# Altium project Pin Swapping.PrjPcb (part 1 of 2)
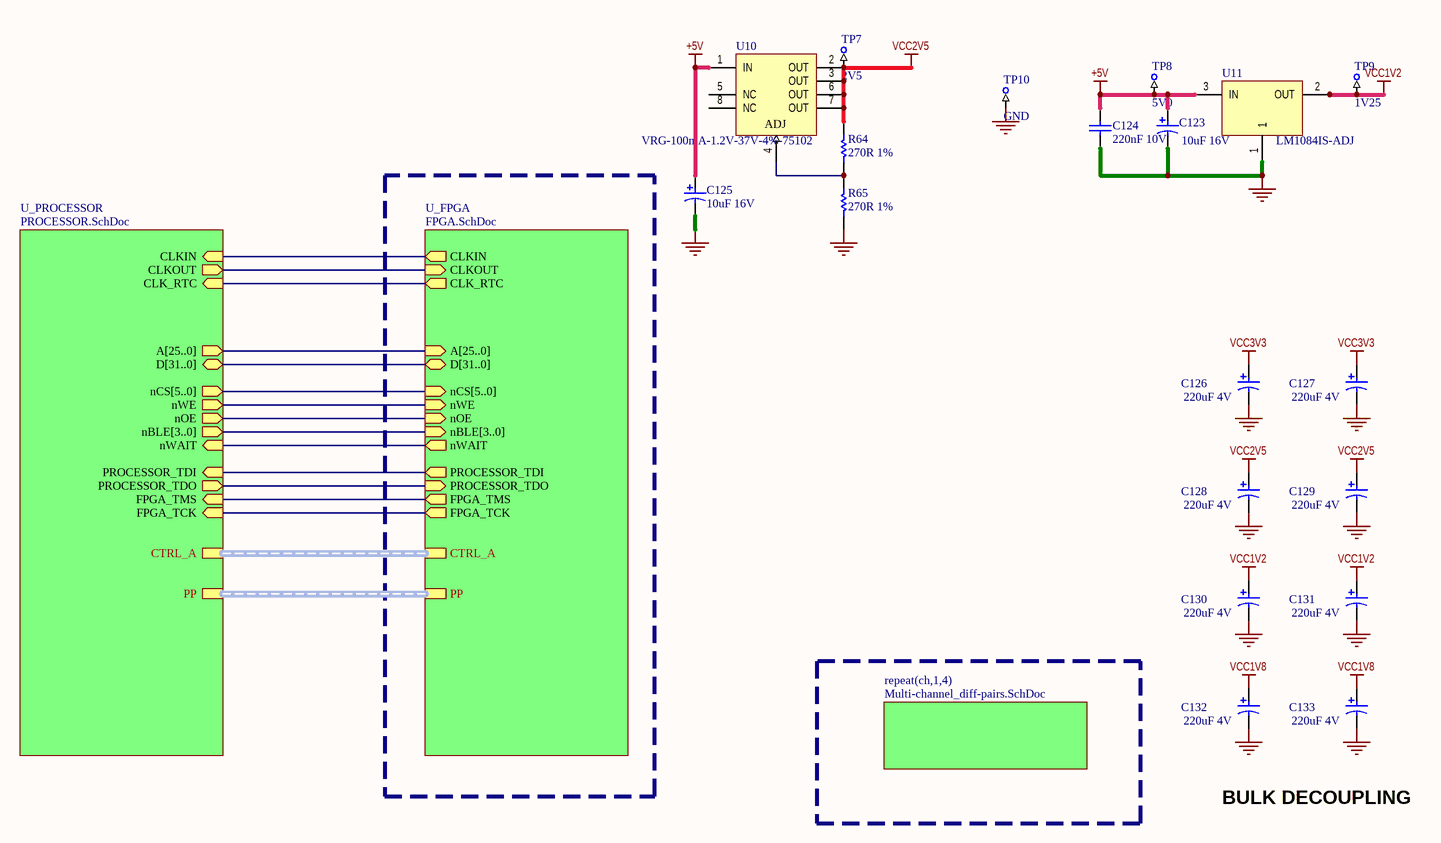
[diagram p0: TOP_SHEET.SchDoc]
6 sheets, 254 parts. Net scope: hierarchical (ports join the sheet entries above them; power ports are global).
Board file: NBP-28 Pin_Swap_Example.PcbDoc
Sheets:
  TOP_SHEET.SchDoc
    U_PROCESSOR = PROCESSOR.SchDoc
      U_PROCESSOR_MEMORIES = PROCESSOR_MEMORIES.SchDoc
    U_FPGA = FPGA.SchDoc
      U_FPGA_RAM = FPGA_MEMORIES.SchDoc
    ch1 = Multi-channel_diff-pairs.SchDoc
    ch2 = Multi-channel_diff-pairs.SchDoc
    ch3 = Multi-channel_diff-pairs.SchDoc
    ch4 = Multi-channel_diff-pairs.SchDoc

## Sheet TOP_SHEET.SchDoc: Pin Swapping
size 431 x 279 mm; DocumentNumber: 1; SheetNumber: 1; SheetTotal: 5

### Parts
C123  10uF 16V  [CAPC3528]
C124  220nF 10V  [CAPC1608]
C125  10uF 16V  [CAPC3528]
C126  220uF 4V  [CAPC7343]
C127  220uF 4V  [CAPC7343]
C128  220uF 4V  [CAPC7343]
C129  220uF 4V  [CAPC7343]
C130  220uF 4V  [CAPC7343]
C131  220uF 4V  [CAPC7343]
C132  220uF 4V  [CAPC7343]
C133  220uF 4V  [CAPC7343]
R64  270R 1%  [RESC2012]
R65  270R 1%  [RESC2012]
TP7  2V5  [TestPin]  (no BOM)
TP8  5V0  [TestPin]  (no BOM)
TP9  1V25  [TestPin]  (no BOM)
TP10  GND  [TestPin]  (no BOM)
U10  VRG-100mA-1.2V-37V-4%-75102  [SOP127P600-8]
U11  LM1084IS-ADJ  [TO254P1435-4]

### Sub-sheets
repeat(ch,1,4) = Multi-channel_diff-pairs.SchDoc: no entries
U_FPGA = FPGA.SchDoc: FPGA_TMS (out), FPGA_TCK (out), PROCESSOR_TDO (in), PROCESSOR_TDI (out), CLKIN (out), A[25..0] (in), D[31..0] (bidir), nBLE[3..0] (in), nWE (in), nOE (in), nCS[5..0] (in), nWAIT (out), CLKOUT (in), CLK_RTC (out), PP (harness PP_13_LINES), CTRL_A (harness P_C_HARNESS)
U_PROCESSOR = PROCESSOR.SchDoc: A[25..0] (out), D[31..0] (bidir), CLKOUT (out), PROCESSOR_TDO (out), PROCESSOR_TDI (in), nBLE[3..0] (out), nWE (out), nOE (out), nCS[5..0] (out), nWAIT (in), CLKIN (in), FPGA_TMS (in), FPGA_TCK (in), CLK_RTC (in), PP (harness PP_13_LINES), CTRL_A (harness P_C_HARNESS)

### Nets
+5V: C123.1 C124.1 C125.1 TP8.1 U10.1(IN) U11.3(IN)
GND: C123.2 C124.2 C125.2 C126.2 C127.2 C128.2 C129.2 C130.2 C131.2 C132.2 C133.2 R65.2 TP10.1 U11.1
VCC1V2: C130.1 C131.1 TP9.1 U11.2(OUT) U11.4(HeatSink)
VCC1V8: C132.1 C133.1
VCC2V5: C128.1 C129.1 R64.1 TP7.1 U10.2(OUT) U10.3(OUT) U10.6(OUT) U10.7(OUT)
VCC3V3: C126.1 C127.1
CLK_RTC: sheet U_PROCESSOR/CLK_RTC, sheet U_FPGA/CLK_RTC
CLKIN: sheet U_PROCESSOR/CLKIN, sheet U_FPGA/CLKIN
CLKOUT: sheet U_PROCESSOR/CLKOUT, sheet U_FPGA/CLKOUT
FPGA_TCK: sheet U_PROCESSOR/FPGA_TCK, sheet U_FPGA/FPGA_TCK
FPGA_TMS: sheet U_PROCESSOR/FPGA_TMS, sheet U_FPGA/FPGA_TMS
nOE: sheet U_PROCESSOR/nOE, sheet U_FPGA/nOE
nWAIT: sheet U_PROCESSOR/nWAIT, sheet U_FPGA/nWAIT
nWE: sheet U_PROCESSOR/nWE, sheet U_FPGA/nWE
PROCESSOR_TDI: sheet U_PROCESSOR/PROCESSOR_TDI, sheet U_FPGA/PROCESSOR_TDI
PROCESSOR_TDO: sheet U_PROCESSOR/PROCESSOR_TDO, sheet U_FPGA/PROCESSOR_TDO
NetR64_2: R64.2 R65.1 U10.4(ADJ)

Not connected (* = marked no-connect by the designer): U10 5(NC) 8(NC)

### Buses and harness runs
bus sheet U_FPGA/A[25..0] = sheet U_PROCESSOR/A[25..0]
bus sheet U_FPGA/D[31..0] = sheet U_PROCESSOR/D[31..0]
bus sheet U_FPGA/nBLE[3..0] = sheet U_PROCESSOR/nBLE[3..0]
bus sheet U_FPGA/nCS[5..0] = sheet U_PROCESSOR/nCS[5..0]
harness sheet U_FPGA/CTRL_A = sheet U_PROCESSOR/CTRL_A
harness sheet U_FPGA/PP = sheet U_PROCESSOR/PP

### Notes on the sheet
- BULK DECOUPLING

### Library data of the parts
C123 C125-C133 = CAP-P: Polar Capacitor
C124 = CAP-NP: Capacitor
R64 R65 = RES: Resistor
TP7-TP10 = TestPin
U10 = VRG-ADJ-8: Low Current 3-Terminal Adjustable Positive Voltage Regulator
U11 = VRG-ADJ-3: 5A Low Dropout Positive Regulators

## Sheet PROCESSOR.SchDoc: Pin Swapping
size 558 x 431 mm; DocumentNumber: 2; SheetNumber: 2; SheetTotal: 6
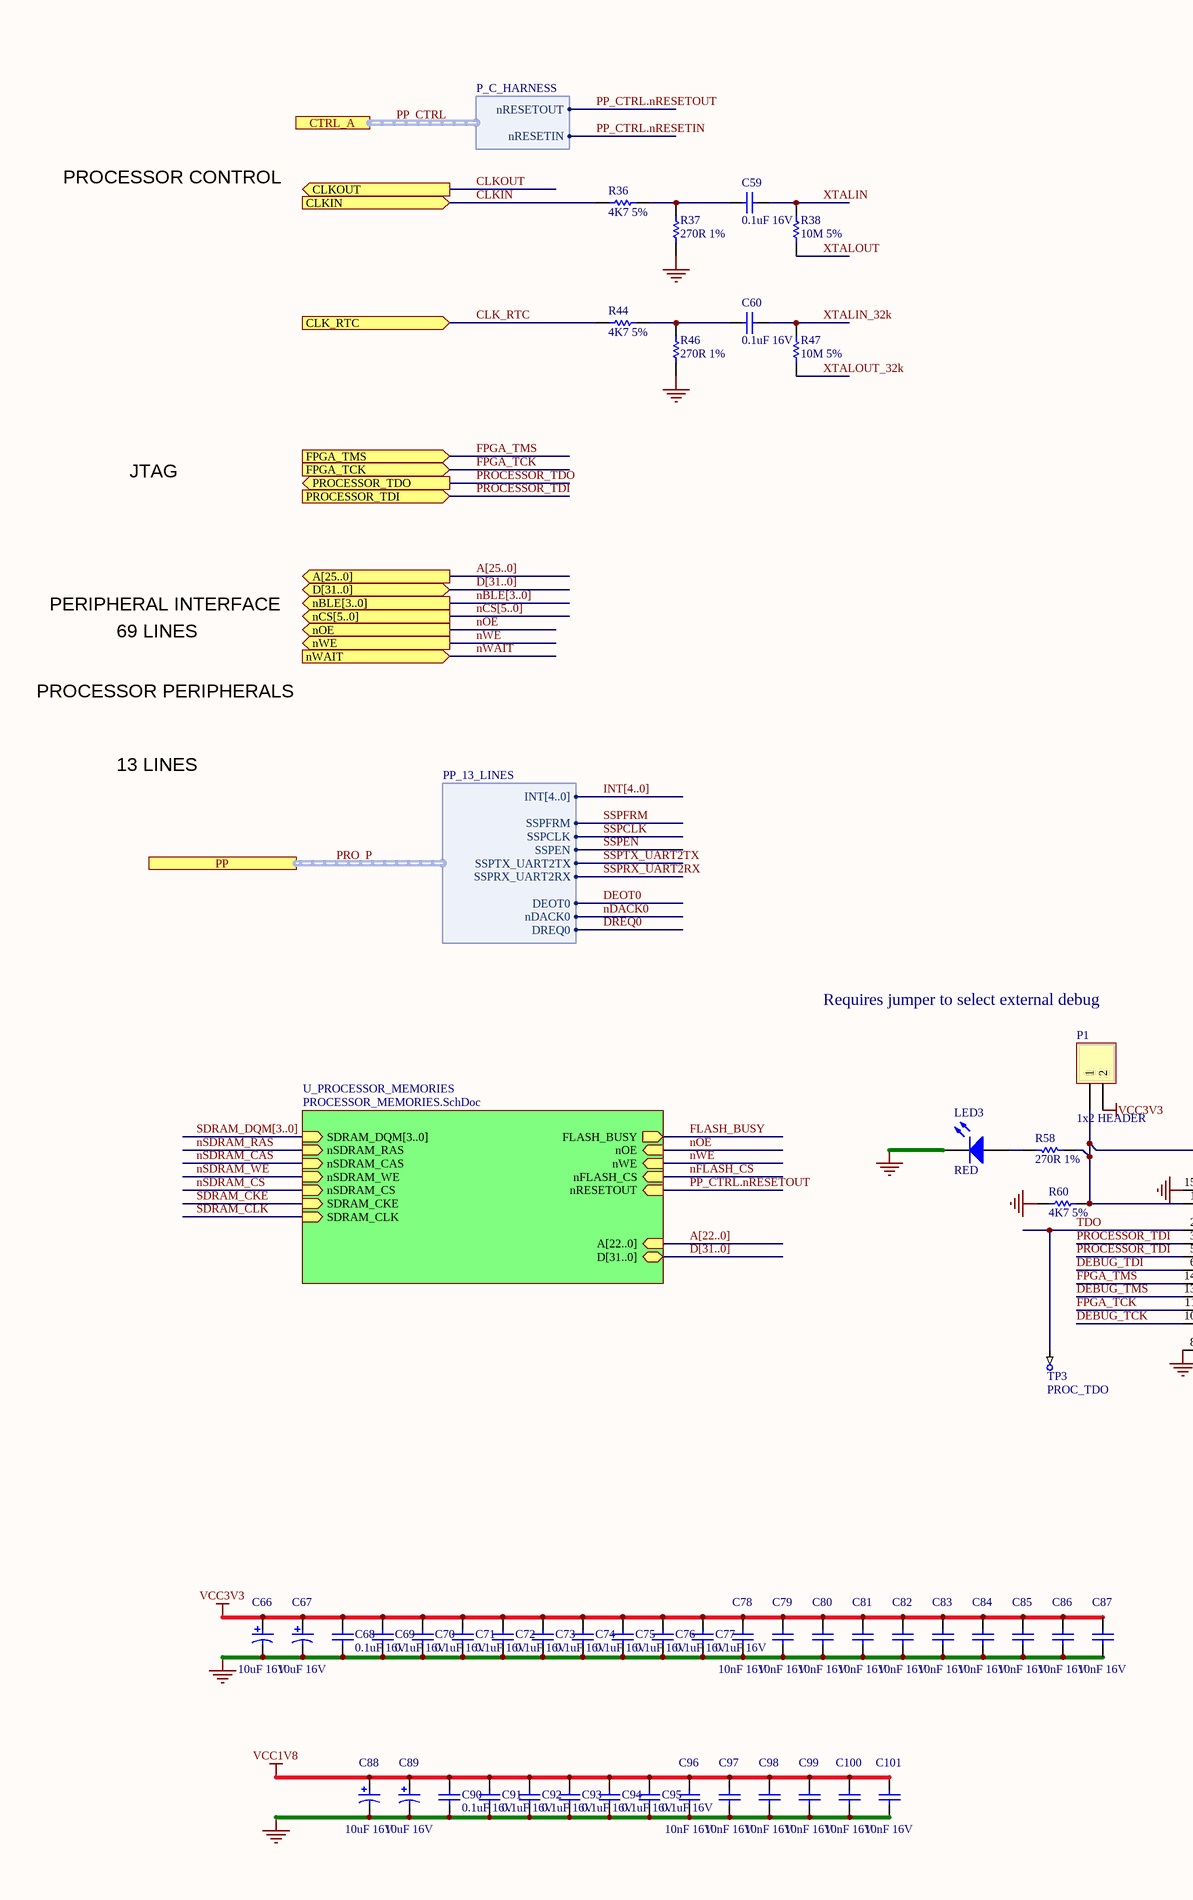
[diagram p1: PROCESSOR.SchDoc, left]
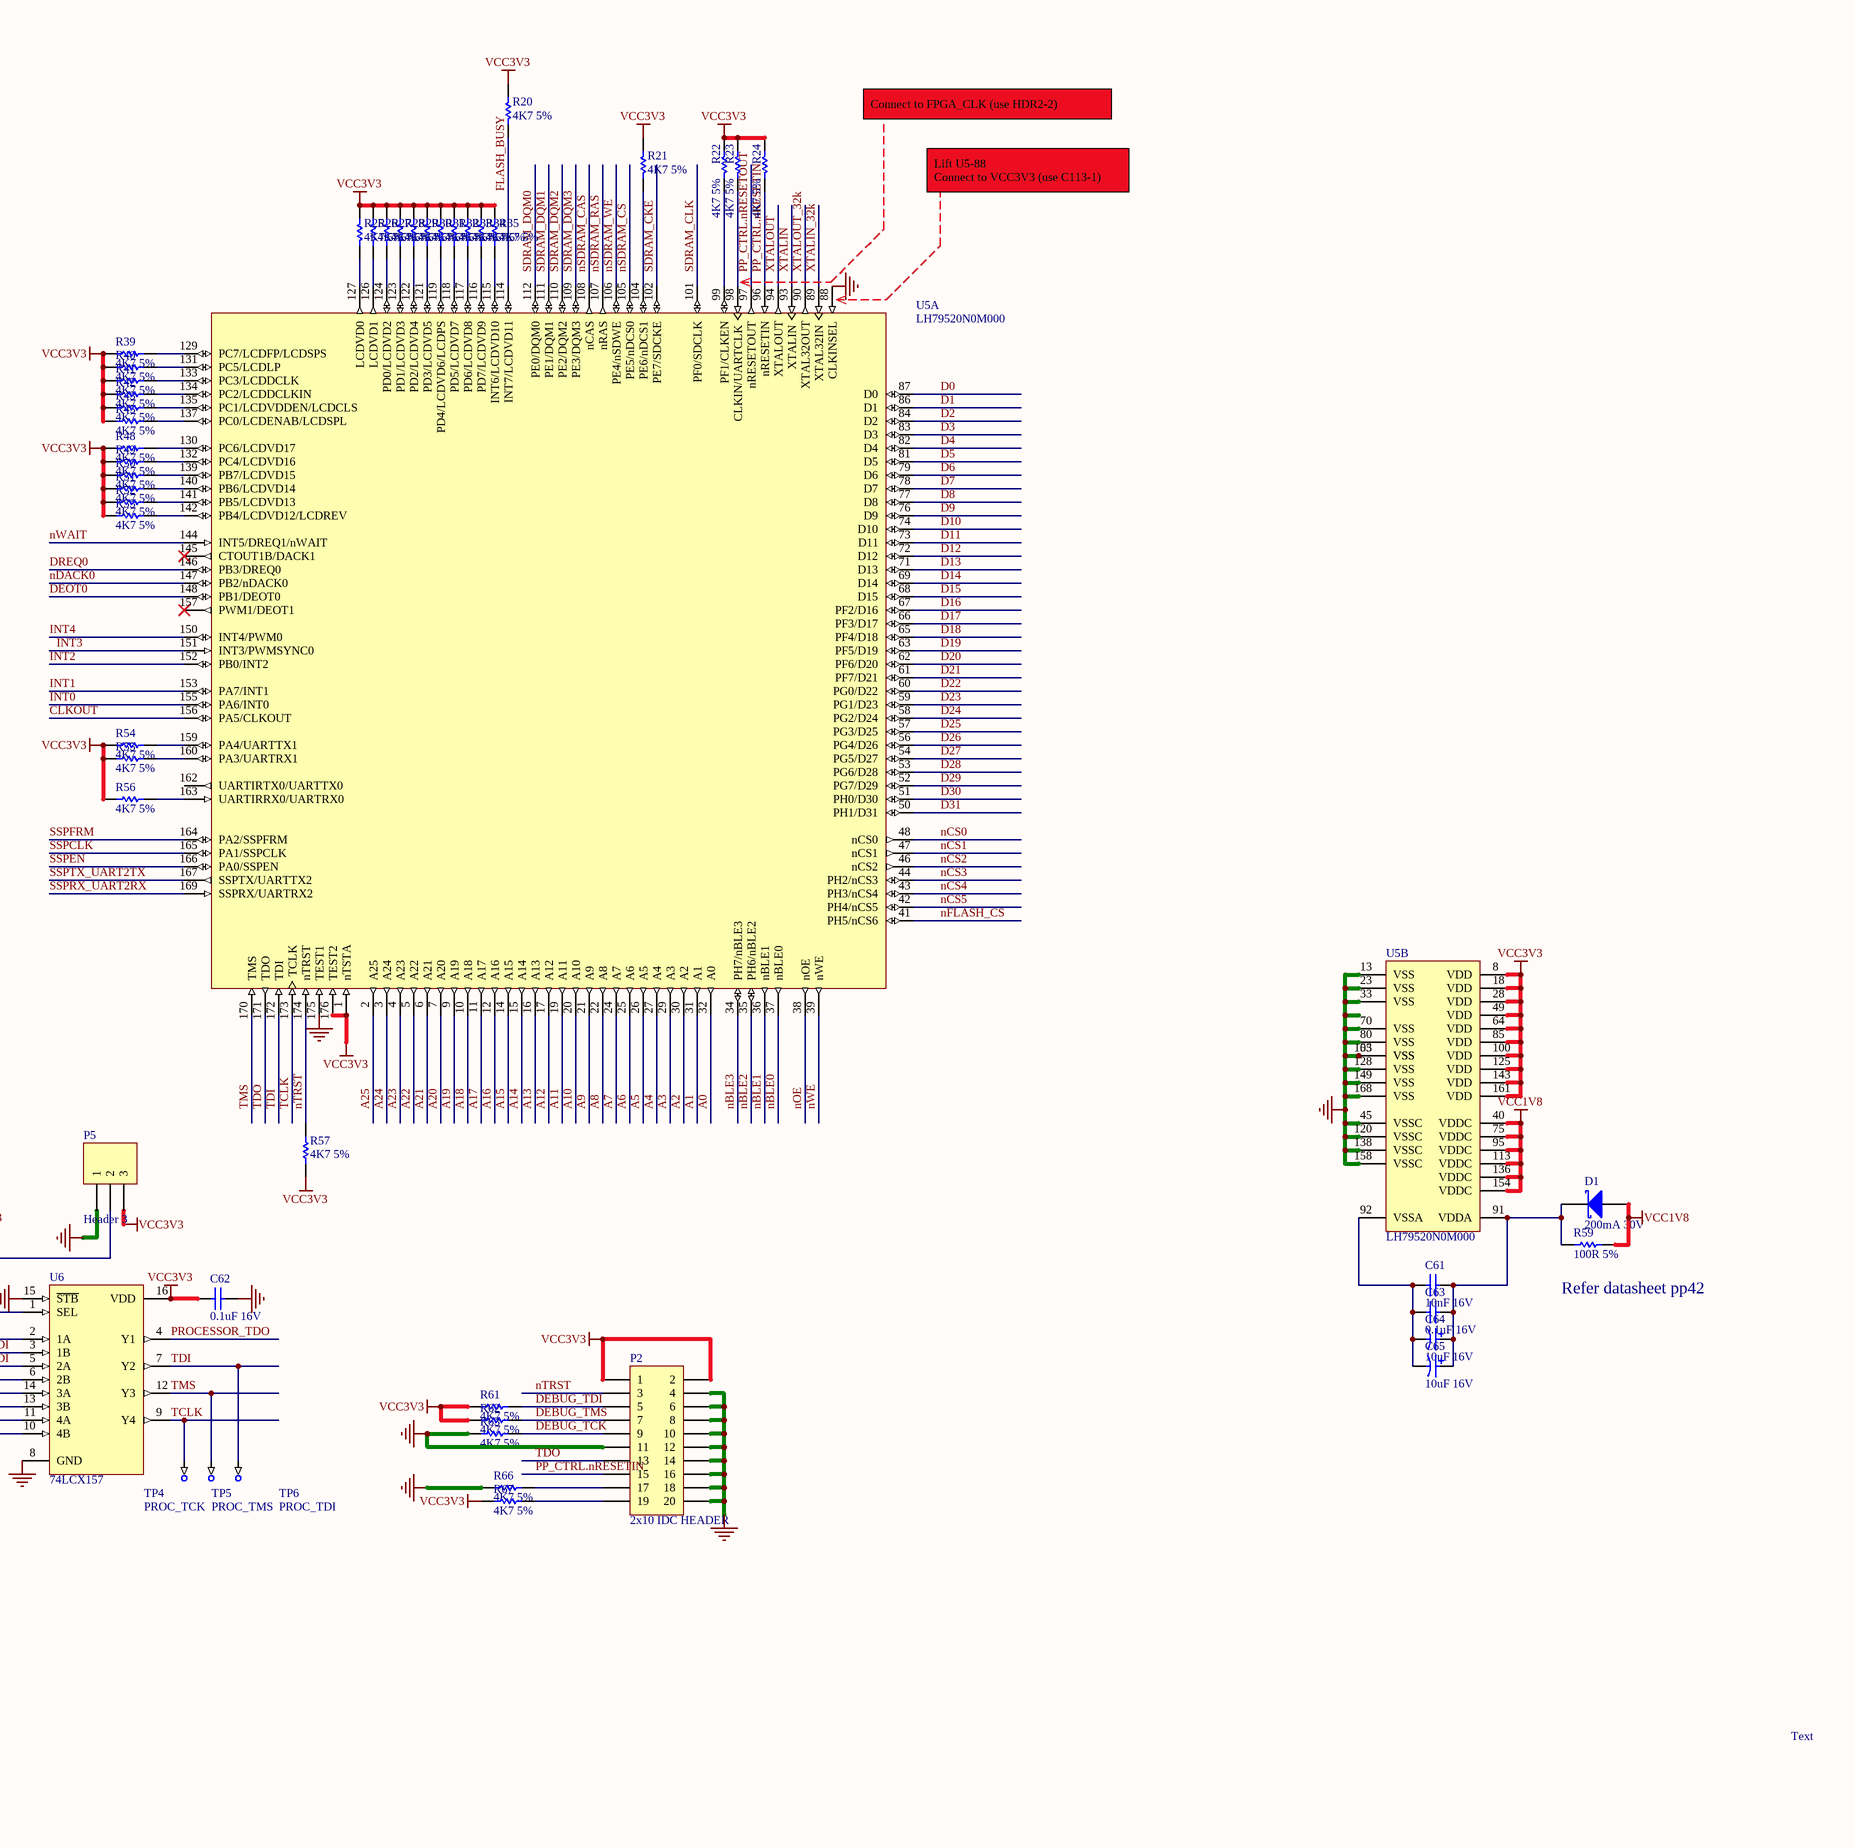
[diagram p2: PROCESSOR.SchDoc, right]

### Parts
C59  0.1uF 16V  [CAPC1005]
C60  0.1uF 16V  [CAPC1005]
C61  10nF 16V  [CAPC1005]
C62  0.1uF 16V  [CAPC1005]
C63  0.1uF 16V  [CAPC1005]
C64  10uF 16V  [CAPC3528]
C65  10uF 16V  [CAPC3528]
C66  10uF 16V  [CAPC3528]
C67  10uF 16V  [CAPC3528]
C68  0.1uF 16V  [CAPC1005]
C69  0.1uF 16V  [CAPC1005]
C70  0.1uF 16V  [CAPC1005]
C71  0.1uF 16V  [CAPC1005]
C72  0.1uF 16V  [CAPC1005]
C73  0.1uF 16V  [CAPC1005]
C74  0.1uF 16V  [CAPC1005]
C75  0.1uF 16V  [CAPC1005]
C76  0.1uF 16V  [CAPC1005]
C77  0.1uF 16V  [CAPC1005]
C78  10nF 16V  [CAPC1005]
C79  10nF 16V  [CAPC1005]
C80  10nF 16V  [CAPC1005]
C81  10nF 16V  [CAPC1005]
C82  10nF 16V  [CAPC1005]
C83  10nF 16V  [CAPC1005]
C84  10nF 16V  [CAPC1005]
C85  10nF 16V  [CAPC1005]
C86  10nF 16V  [CAPC1005]
C87  10nF 16V  [CAPC1005]
C88  10uF 16V  [CAPC3528]
C89  10uF 16V  [CAPC3528]
C90  0.1uF 16V  [CAPC1005]
C91  0.1uF 16V  [CAPC1005]
C92  0.1uF 16V  [CAPC1005]
C93  0.1uF 16V  [CAPC1005]
C94  0.1uF 16V  [CAPC1005]
C95  0.1uF 16V  [CAPC1005]
C96  10nF 16V  [CAPC1005]
C97  10nF 16V  [CAPC1005]
C98  10nF 16V  [CAPC1005]
C99  10nF 16V  [CAPC1005]
C100  10nF 16V  [CAPC1005]
C101  10nF 16V  [CAPC1005]
D1  200mA 30V  [SOT95P230-3]
LED3  RED  [LED2013]
P1  1x2 HEADER  [HDR1X2]
P2  2x10 IDC HEADER  [IDC2.54-V20D]
P5  Header 3  [HDR1X3]
R20  4K7 5%  [RESC1005]
R21  4K7 5%  [RESC1005]
R22  4K7 5%  [RESC1005]
R23  4K7 5%  [RESC1005]
R24  4K7 5%  [RESC1005]
R25  4K7 5%  [RESC1005]
R26  4K7 5%  [RESC1005]
R27  4K7 5%  [RESC1005]
R28  4K7 5%  [RESC1005]
R29  4K7 5%  [RESC1005]
R30  4K7 5%  [RESC1005]
R31  4K7 5%  [RESC1005]
R32  4K7 5%  [RESC1005]
R33  4K7 5%  [RESC1005]
R34  4K7 5%  [RESC1005]
R35  4K7 5%  [RESC1005]
R36  4K7 5%  [RESC1005]
R37  270R 1%  [RESC2012]
R38  10M 5%  [RESC2012]
R39  4K7 5%  [RESC1005]
R40  4K7 5%  [RESC1005]
R41  4K7 5%  [RESC1005]
R42  4K7 5%  [RESC1005]
R43  4K7 5%  [RESC1005]
R44  4K7 5%  [RESC1005]
R45  4K7 5%  [RESC1005]
R46  270R 1%  [RESC2012]
R47  10M 5%  [RESC2012]
R48  4K7 5%  [RESC1005]
R49  4K7 5%  [RESC1005]
R50  4K7 5%  [RESC1005]
R51  4K7 5%  [RESC1005]
R52  4K7 5%  [RESC1005]
R53  4K7 5%  [RESC1005]
R54  4K7 5%  [RESC1005]
R55  4K7 5%  [RESC1005]
R56  4K7 5%  [RESC1005]
R57  4K7 5%  [RESC1005]
R58  270R 1%  [RESC2012]
R59  100R 5%  [RESC2012]
R60  4K7 5%  [RESC1005]
R61  4K7 5%  [RESC1005]
R62  4K7 5%  [RESC1005]
R63  4K7 5%  [RESC1005]
R66  4K7 5%  [RESC1005]
R67  4K7 5%  [RESC1005]
TP3  PROC_TDO  [TestPin]  (no BOM)
TP4  PROC_TCK  [TestPin]  (no BOM)
TP5  PROC_TMS  [TestPin]  (no BOM)
TP6  PROC_TDI  [TestPin]  (no BOM)
U5  LH79520N0M000  [QFP40P2000X2000-176]  (parts A,B of 2)
U6  74LCX157  [TSOP65P638-16]

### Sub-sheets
U_PROCESSOR_MEMORIES = PROCESSOR_MEMORIES.SchDoc: SDRAM_DQM[3..0] (in), nSDRAM_RAS (in), nSDRAM_CAS (in), nSDRAM_WE (in), nSDRAM_CS (in), SDRAM_CKE (in), SDRAM_CLK (in), A[22..0] (in), D[31..0] (bidir), nOE (in), nWE (in), nFLASH_CS (in), nRESETOUT (in), FLASH_BUSY (out)

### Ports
A[25..0] (out), CLK_RTC (in), CLKIN (in), CLKOUT (out), CTRL_A (harness P_C_HARNESS), D[31..0] (bidir), FPGA_TCK (in), FPGA_TMS (in), nBLE[3..0] (out), nCS[5..0] (out), nOE (out), nWAIT (in), nWE (out), PP (harness PP_13_LINES), PROCESSOR_TDI (in), PROCESSOR_TDO (out)

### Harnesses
PP_13_LINES: INT[4..0], SSPFRM, SSPCLK, SSPEN, SSPTX_UART2TX, SSPRX_UART2RX, DEOT0, nDACK0, DREQ0
P_C_HARNESS: nRESETOUT, nRESETIN

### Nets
GND: C62.2 C66.2 C67.2 C68.2 C69.2 C70.2 C71.2 C72.2 C73.2 C74.2 C75.2 C76.2 C77.2 C78.2 C79.2 C80.2 C81.2 C82.2 C83.2 C84.2 C85.2 C86.2 C87.2 C88.2 C89.2 C90.2 C91.2 C92.2 C93.2 C94.2 C95.2 C96.2 C97.2 C98.2 C99.2 C100.2 C101.2 LED3.2(K) P2.4 P2.6 P2.8 P2.10 P2.11 P2.12 P2.14 P2.16 P2.18 P2.20 P5.1 R37.1 R46.1 R60.2 R63.1 R66.1 U5.13(VSS) U5.23(VSS) U5.33(VSS) U5.45(VSSC) U5.55(VSS) U5.70(VSS) U5.80(VSS) U5.88(CLKINSEL) U5.103(VSS) U5.120(VSSC) U5.128(VSS) U5.138(VSSC) U5.149(VSS) U5.158(VSSC) U5.168(VSS) U5.175(TEST1) U6.8(GND) U6.15(~{STB})
VCC1V8: C88.1 C89.1 C90.1 C91.1 C92.1 C93.1 C94.1 C95.1 C96.1 C97.1 C98.1 C99.1 C100.1 C101.1 D1.1(A) R59.1 U5.40(VDDC) U5.75(VDDC) U5.95(VDDC) U5.113(VDDC) U5.136(VDDC) U5.154(VDDC)
VCC3V3: C62.1 C66.1 C67.1 C68.1 C69.1 C70.1 C71.1 C72.1 C73.1 C74.1 C75.1 C76.1 C77.1 C78.1 C79.1 C80.1 C81.1 C82.1 C83.1 C84.1 C85.1 C86.1 C87.1 P1.2 P2.1 P2.2 P5.3 R20.2 R21.2 R22.2 R23.2 R24.2 R25.2 R26.2 R27.2 R28.2 R29.2 R30.2 R31.2 R32.2 R33.2 R34.2 R35.2 R39.2 R40.2 R41.2 R42.2 R43.2 R45.2 R48.2 R49.2 R50.2 R51.2 R52.2 R53.2 R54.2 R55.2 R56.2 R57.2 R61.1 R62.1 R67.1 U5.1(nTSTA) U5.8(VDD) U5.18(VDD) U5.28(VDD) U5.49(VDD) U5.64(VDD) U5.85(VDD) U5.100(VDD) U5.125(VDD) U5.143(VDD) U5.161(VDD) U5.176(TEST2) U6.16(VDD)
A0: U5.32(A0)
A1: U5.31(A1)
A2: U5.30(A2)
A3: U5.29(A3)
A4: U5.27(A4)
A5: U5.26(A5)
A6: U5.25(A6)
A7: U5.24(A7)
A8: U5.22(A8)
A9: U5.21(A9)
A10: U5.20(A10)
A11: U5.19(A11)
A12: U5.17(A12)
A13: U5.16(A13)
A14: U5.15(A14)
A15: U5.14(A15)
A16: U5.12(A16)
A17: U5.11(A17)
A18: U5.10(A18)
A19: U5.9(A19)
A20: U5.7(A20)
A21: U5.6(A21)
A22: U5.5(A22)
A23: U5.4(A23)
A24: U5.3(A24)
A25: U5.2(A25)
CLK_RTC: R44.2 ; port CLK_RTC
CLKIN: R36.2 ; port CLKIN
CLKOUT: U5.156(PA5/CLKOUT) ; port CLKOUT
D0: U5.87(D0)
D1: U5.86(D1)
D2: U5.84(D2)
D3: U5.83(D3)
D4: U5.82(D4)
D5: U5.81(D5)
D6: U5.79(D6)
D7: U5.78(D7)
D8: U5.77(D8)
D9: U5.76(D9)
D10: U5.74(D10)
D11: U5.73(D11)
D12: U5.72(D12)
D13: U5.71(D13)
D14: U5.69(D14)
D15: U5.68(D15)
D16: U5.67(PF2/D16)
D17: U5.66(PF3/D17)
D18: U5.65(PF4/D18)
D19: U5.63(PF5/D19)
D20: U5.62(PF6/D20)
D21: U5.61(PF7/D21)
D22: U5.60(PG0/D22)
D23: U5.59(PG1/D23)
D24: U5.58(PG2/D24)
D25: U5.57(PG3/D25)
D26: U5.56(PG4/D26)
D27: U5.54(PG5/D27)
D28: U5.53(PG6/D28)
D29: U5.52(PG7/D29)
D30: U5.51(PH0/D30)
D31: U5.50(PH1/D31)
DEBUG_TCK: P2.9 R63.2 U6.10(4B)
DEBUG_TDI: P2.5 R61.2 U6.6(2B)
DEBUG_TMS: P2.7 R62.2 U6.13(3B)
DEOT0: U5.148(PB1/DEOT0) ; port PP.DEOT0
DREQ0: U5.146(PB3/DREQ0) ; port PP.DREQ0
FLASH_BUSY: R20.1 U5.114(INT7/LCDVD11) ; sheet U_PROCESSOR_MEMORIES/FLASH_BUSY
FPGA_TCK: U6.11(4A) ; port FPGA_TCK
FPGA_TMS: U6.14(3A) ; port FPGA_TMS
INT0: U5.155(PA6/INT0)
INT1: U5.153(PA7/INT1)
INT2: U5.152(PB0/INT2)
INT3: U5.151(INT3/PWMSYNC0)
INT4: U5.150(INT4/PWM0)
nBLE0: U5.37(nBLE0)
nBLE1: U5.36(nBLE1)
nBLE2: U5.35(PH6/nBLE2)
nBLE3: U5.34(PH7/nBLE3)
nCS0: U5.48(nCS0)
nCS1: U5.47(nCS1)
nCS2: U5.46(nCS2)
nCS3: U5.44(PH2/nCS3)
nCS4: U5.43(PH3/nCS4)
nCS5: U5.42(PH4/nCS5)
nDACK0: U5.147(PB2/nDACK0) ; port PP.nDACK0
nFLASH_CS: U5.41(PH5/nCS6) ; sheet U_PROCESSOR_MEMORIES/nFLASH_CS
nOE: U5.38(nOE) ; port nOE, sheet U_PROCESSOR_MEMORIES/nOE
nSDRAM_CAS: U5.108(nCAS) ; sheet U_PROCESSOR_MEMORIES/nSDRAM_CAS
nSDRAM_CS: U5.105(PE5/nDCS0) ; sheet U_PROCESSOR_MEMORIES/nSDRAM_CS
nSDRAM_RAS: U5.107(nRAS) ; sheet U_PROCESSOR_MEMORIES/nSDRAM_RAS
nSDRAM_WE: U5.106(PE4/nSDWE) ; sheet U_PROCESSOR_MEMORIES/nSDRAM_WE
nTRST: P2.3 R57.1 U5.174(nTRST)
nWAIT: U5.144(INT5/DREQ1/nWAIT) ; port nWAIT
nWE: U5.39(nWE) ; port nWE, sheet U_PROCESSOR_MEMORIES/nWE
PP_CTRL.nRESETIN: P2.15 R24.1 U5.96(nRESETIN) ; port CTRL_A.nRESETIN
PP_CTRL.nRESETOUT: U5.97(nRESETOUT) ; sheet U_PROCESSOR_MEMORIES/nRESETOUT, port CTRL_A.nRESETOUT  [project net nRESETOUT]
PROCESSOR_TDI: U6.3(1B) U6.5(2A) ; port PROCESSOR_TDI
PROCESSOR_TDO: U6.4(Y1) ; port PROCESSOR_TDO
SDRAM_CKE: U5.102(PE7/SDCKE) ; sheet U_PROCESSOR_MEMORIES/SDRAM_CKE
SDRAM_CLK: U5.101(PF0/SDCLK) ; sheet U_PROCESSOR_MEMORIES/SDRAM_CLK
SDRAM_DQM0: U5.112(PE0/DQM0)
SDRAM_DQM1: U5.111(PE1/DQM1)
SDRAM_DQM2: U5.110(PE2/DQM2)
SDRAM_DQM3: U5.109(PE3/DQM3)
SSPCLK: U5.165(PA1/SSPCLK) ; port PP.SSPCLK  [project net PRO_P.SSPCLK]
SSPEN: U5.166(PA0/SSPEN) ; port PP.SSPEN  [project net PRO_P.SSPEN]
SSPFRM: U5.164(PA2/SSPFRM) ; port PP.SSPFRM  [project net PRO_P.SSPFRM]
SSPRX_UART2RX: U5.169(SSPRX/UARTRX2) ; port PP.SSPRX_UART2RX  [project net PRO_P.SSPRX_UART2RX]
SSPTX_UART2TX: U5.167(SSPTX/UARTTX2) ; port PP.SSPTX_UART2TX  [project net PRO_P.SSPTX_UART2TX]
TCLK: TP4.1 U5.173(TCLK) U6.9(Y4)
TDI: TP6.1 U5.172(TDI) U6.7(Y2)
TDO: P2.13 TP3.1 U5.171(TDO) U6.2(1A)
TMS: TP5.1 U5.170(TMS) U6.12(Y3)
XTALIN: C59.2 R38.1 U5.93(XTALIN)
XTALIN_32k: C60.2 R47.1 U5.89(XTAL32IN)
XTALOUT: R38.2 U5.94(XTALOUT)
XTALOUT_32k: R47.2 U5.90(XTAL32OUT)
NetC59_1: C59.1 R36.1 R37.2
NetC60_1: C60.1 R44.1 R46.2
NetC61_1: C61.1 C63.1 C64.1 C65.1 D1.3(k) R59.2 U5.91(VDDA)
NetC61_2: C61.2 C63.2 C64.2 C65.2 U5.92(VSSA)
NetLED3_1: LED3.1(A) R58.2
NetP1_1: P1.1 P5.2 R58.1 R60.1 U6.1(SEL)
NetP2_17: P2.17 R66.2
NetP2_19: P2.19 R67.2
NetR21_1: R21.1 U5.104(PE6/nDCS1)
NetR22_1: R22.1 U5.99(PF1/CLKEN)
NetR23_1: R23.1 U5.98(CLKIN/UARTCLK)
NetR25_1: R25.1 U5.127(LCDVD0)
NetR26_1: R26.1 U5.126(LCDVD1)
NetR27_1: R27.1 U5.124(PD0/LCDVD2)
NetR28_1: R28.1 U5.123(PD1/LCDVD3)
NetR29_1: R29.1 U5.122(PD2/LCDVD4)
NetR30_1: R30.1 U5.121(PD3/LCDVD5)
NetR31_1: R31.1 U5.119(PD4/LCDVD6/LCDPS)
NetR32_1: R32.1 U5.118(PD5/LCDVD7)
NetR33_1: R33.1 U5.117(PD6/LCDVD8)
NetR34_1: R34.1 U5.116(PD7/LCDVD9)
NetR35_1: R35.1 U5.115(INT6/LCDVD10)
NetR39_1: R39.1 U5.129(PC7/LCDFP/LCDSPS)
NetR40_1: R40.1 U5.131(PC5/LCDLP)
NetR41_1: R41.1 U5.133(PC3/LCDDCLK)
NetR42_1: R42.1 U5.134(PC2/LCDDCLKIN)
NetR43_1: R43.1 U5.135(PC1/LCDVDDEN/LCDCLS)
NetR45_1: R45.1 U5.137(PC0/LCDENAB/LCDSPL)
NetR48_1: R48.1 U5.130(PC6/LCDVD17)
NetR49_1: R49.1 U5.132(PC4/LCDVD16)
NetR50_1: R50.1 U5.139(PB7/LCDVD15)
NetR51_1: R51.1 U5.140(PB6/LCDVD14)
NetR52_1: R52.1 U5.141(PB5/LCDVD13)
NetR53_1: R53.1 U5.142(PB4/LCDVD12/LCDREV)
NetR54_1: R54.1 U5.159(PA4/UARTTX1)
NetR55_1: R55.1 U5.160(PA3/UARTRX1)
NetR56_1: R56.1 U5.163(UARTIRRX0/UARTRX0)

Not connected (* = marked no-connect by the designer): D1 2; U5 145(CTOUT1B/DACK1)* 157(PWM1/DEOT1)* 162(UARTIRTX0/UARTTX0)

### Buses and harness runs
bus A[22..0] = sheet U_PROCESSOR_MEMORIES/A[22..0]
bus A[25..0] = port A[25..0]
bus D[31..0] = port D[31..0]
bus D[31..0] = sheet U_PROCESSOR_MEMORIES/D[31..0]
bus INT[4..0]
bus nBLE[3..0] = port nBLE[3..0]
bus nCS[5..0] = port nCS[5..0]
bus SDRAM_DQM[3..0] = sheet U_PROCESSOR_MEMORIES/SDRAM_DQM[3..0]
harness PP_CTRL = port CTRL_A
harness PRO_P = port PP

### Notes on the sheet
- Connect to FPGA_CLK (use HDR2-2)
- Lift U5-88
  Connect to VCC3V3 (use C113-1)
- PROCESSOR CONTROL
- JTAG
- PERIPHERAL INTERFACE
- 69 LINES
- PROCESSOR PERIPHERALS
- 13 LINES
- Requires jumper to select external debug
- (near R59) Refer datasheet pp42
- Text

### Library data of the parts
C59-C63 C68-C87 C90-C101 = CAP-NP: Capacitor
C64-C67 C88 C89 = CAP-P: Polar Capacitor
D1 = DIO-SCHOTTKY-1S-SOT23: Schottky Barrier Double Diode
LED3 = DIO-LED-1S: Typical GREEN SMD LED Agilent make
P1 = CON-HDR-1x2-STR: Header, 2-Pin
P2 = CON-IDC-2x10-M-STR: 10x2 IDC Male PCB Box Header
P5 = Header 3: Header, 3-Pin
R20-R63 R66 R67 = RES: Resistor
TP3-TP6 = TestPin
U5 = LH79520N0M000: 32-Bit ARM720T-Based BlueStreak MCU with 8KB Cache, MMU, Color LCD controller, 32KB SRAM, 176-Pin LQFP
U6 = 74LCX157-TSOP16: Quad 2-Input Multiplexer

## Sheet PROCESSOR_MEMORIES.SchDoc: Pin Swapping
size 431 x 279 mm; DocumentNumber: 3; SheetNumber: 3; SheetTotal: 5
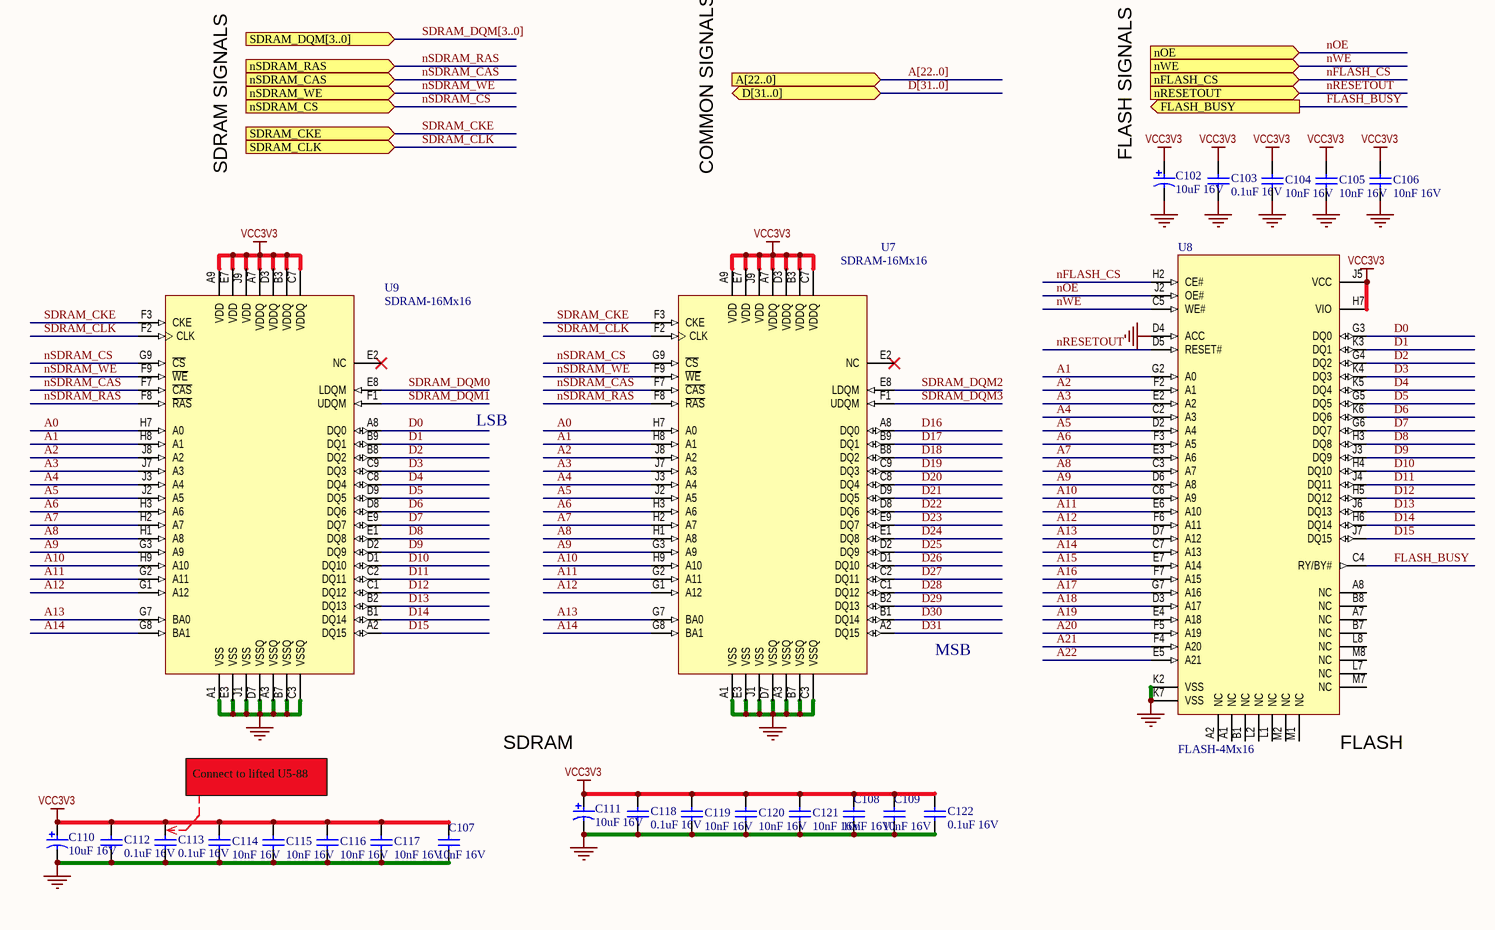
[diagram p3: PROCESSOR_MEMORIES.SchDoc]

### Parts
C102  10uF 16V  [CAPC3528]
C103  0.1uF 16V  [CAPC1005]
C104  10nF 16V  [CAPC1005]
C105  10nF 16V  [CAPC1005]
C106  10nF 16V  [CAPC1005]
C107  10nF 16V  [CAPC1005]
C108  10nF 16V  [CAPC1005]
C109  10nF 16V  [CAPC1005]
C110  10uF 16V  [CAPC3528]
C111  10uF 16V  [CAPC3528]
C112  0.1uF 16V  [CAPC1005]
C113  0.1uF 16V  [CAPC1005]
C114  10nF 16V  [CAPC1005]
C115  10nF 16V  [CAPC1005]
C116  10nF 16V  [CAPC1005]
C117  10nF 16V  [CAPC1005]
C118  0.1uF 16V  [CAPC1005]
C119  10nF 16V  [CAPC1005]
C120  10nF 16V  [CAPC1005]
C121  10nF 16V  [CAPC1005]
C122  0.1uF 16V  [CAPC1005]
U7  SDRAM-16Mx16  [BGA80P9X6-54]
U8  FLASH-4Mx16  [BGA80P12X8-63]
U9  SDRAM-16Mx16  [BGA80P9X6-54]

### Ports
A[22..0] (in), D[31..0] (bidir), FLASH_BUSY (out), nFLASH_CS (in), nOE (in), nRESETOUT (in), nSDRAM_CAS (in), nSDRAM_CS (in), nSDRAM_RAS (in), nSDRAM_WE (in), nWE (in), SDRAM_CKE (in), SDRAM_CLK (in), SDRAM_DQM[3..0] (in)

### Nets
GND: C102.2 C103.2 C104.2 C105.2 C106.2 C107.2 C108.2 C109.2 C110.2 C111.2 C112.2 C113.2 C114.2 C115.2 C116.2 C117.2 C118.2 C119.2 C120.2 C121.2 C122.2 U7.A1(VSS) U7.A3(VSSQ) U7.B7(VSSQ) U7.C3(VSSQ) U7.D7(VSSQ) U7.E3(VSS) U7.J1(VSS) U8.D4(ACC) U8.K2(VSS) U8.K7(VSS) U9.A1(VSS) U9.A3(VSSQ) U9.B7(VSSQ) U9.C3(VSSQ) U9.D7(VSSQ) U9.E3(VSS) U9.J1(VSS)
VCC3V3: C102.1 C103.1 C104.1 C105.1 C106.1 C107.1 C108.1 C109.1 C110.1 C111.1 C112.1 C113.1 C114.1 C115.1 C116.1 C117.1 C118.1 C119.1 C120.1 C121.1 C122.1 U7.A7(VDDQ) U7.A9(VDD) U7.B3(VDDQ) U7.C7(VDDQ) U7.D3(VDDQ) U7.E7(VDD) U7.J9(VDD) U8.H7(VIO) U8.J5(VCC) U9.A7(VDDQ) U9.A9(VDD) U9.B3(VDDQ) U9.C7(VDDQ) U9.D3(VDDQ) U9.E7(VDD) U9.J9(VDD)
A0: U7.H7(A0) U9.H7(A0)
A1: U7.H8(A1) U8.G2(A0) U9.H8(A1)
A2: U7.J8(A2) U8.F2(A1) U9.J8(A2)
A3: U7.J7(A3) U8.E2(A2) U9.J7(A3)
A4: U7.J3(A4) U8.C2(A3) U9.J3(A4)
A5: U7.J2(A5) U8.D2(A4) U9.J2(A5)
A6: U7.H3(A6) U8.F3(A5) U9.H3(A6)
A7: U7.H2(A7) U8.E3(A6) U9.H2(A7)
A8: U7.H1(A8) U8.C3(A7) U9.H1(A8)
A9: U7.G3(A9) U8.D6(A8) U9.G3(A9)
A10: U7.H9(A10) U8.C6(A9) U9.H9(A10)
A11: U7.G2(A11) U8.E6(A10) U9.G2(A11)
A12: U7.G1(A12) U8.F6(A11) U9.G1(A12)
A13: U7.G7(BA0) U8.D7(A12) U9.G7(BA0)
A14: U7.G8(BA1) U8.C7(A13) U9.G8(BA1)
A15: U8.E7(A14)
A16: U8.F7(A15)
A17: U8.G7(A16)
A18: U8.D3(A17)
A19: U8.E4(A18)
A20: U8.F5(A19)
A21: U8.F4(A20)
A22: U8.E5(A21)
D0: U8.G3(DQ0) U9.A8(DQ0)
D1: U8.K3(DQ1) U9.B9(DQ1)
D2: U8.G4(DQ2) U9.B8(DQ2)
D3: U8.K4(DQ3) U9.C9(DQ3)
D4: U8.K5(DQ4) U9.C8(DQ4)
D5: U8.G5(DQ5) U9.D9(DQ5)
D6: U8.K6(DQ6) U9.D8(DQ6)
D7: U8.G6(DQ7) U9.E9(DQ7)
D8: U8.H3(DQ8) U9.E1(DQ8)
D9: U8.J3(DQ9) U9.D2(DQ9)
D10: U8.H4(DQ10) U9.D1(DQ10)
D11: U8.J4(DQ11) U9.C2(DQ11)
D12: U8.H5(DQ12) U9.C1(DQ12)
D13: U8.J6(DQ13) U9.B2(DQ13)
D14: U8.H6(DQ14) U9.B1(DQ14)
D15: U8.J7(DQ15) U9.A2(DQ15)
D16: U7.A8(DQ0)
D17: U7.B9(DQ1)
D18: U7.B8(DQ2)
D19: U7.C9(DQ3)
D20: U7.C8(DQ4)
D21: U7.D9(DQ5)
D22: U7.D8(DQ6)
D23: U7.E9(DQ7)
D24: U7.E1(DQ8)
D25: U7.D2(DQ9)
D26: U7.D1(DQ10)
D27: U7.C2(DQ11)
D28: U7.C1(DQ12)
D29: U7.B2(DQ13)
D30: U7.B1(DQ14)
D31: U7.A2(DQ15)
FLASH_BUSY: U8.C4(RY/BY#) ; port FLASH_BUSY
nFLASH_CS: U8.H2(CE#) ; port nFLASH_CS
nOE: U8.J2(OE#) ; port nOE
nRESETOUT: U8.D5(RESET#) ; port nRESETOUT
nSDRAM_CAS: U7.F7(~{CAS}) U9.F7(~{CAS}) ; port nSDRAM_CAS
nSDRAM_CS: U7.G9(~{CS}) U9.G9(~{CS}) ; port nSDRAM_CS
nSDRAM_RAS: U7.F8(~{RAS}) U9.F8(~{RAS}) ; port nSDRAM_RAS
nSDRAM_WE: U7.F9(~{WE}) U9.F9(~{WE}) ; port nSDRAM_WE
nWE: U8.C5(WE#) ; port nWE
SDRAM_CKE: U7.F3(CKE) U9.F3(CKE) ; port SDRAM_CKE
SDRAM_CLK: U7.F2(CLK) U9.F2(CLK) ; port SDRAM_CLK
SDRAM_DQM0: U9.E8(LDQM)
SDRAM_DQM1: U9.F1(UDQM)
SDRAM_DQM2: U7.E8(LDQM)
SDRAM_DQM3: U7.F1(UDQM)

Not connected (* = marked no-connect by the designer): U7 E2(NC)*; U8 A1(NC) A2(NC) A7(NC) A8(NC) B1(NC) B7(NC) B8(NC) L1(NC) L2(NC) L7(NC) L8(NC) M1(NC) M2(NC) M7(NC) M8(NC); U9 E2(NC)*

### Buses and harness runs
bus A[22..0] = port A[22..0]
bus D[31..0] = port D[31..0]
bus SDRAM_DQM[3..0] = port SDRAM_DQM[3..0]

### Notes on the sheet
- SDRAM SIGNALS
- COMMON SIGNALS
- (near C102) FLASH SIGNALS
- LSB
- MSB
- Connect to lifted U5-88
- SDRAM
- (near U8) FLASH

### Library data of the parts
C102 C110 C111 = CAP-P: Polar Capacitor
C103-C109 C112-C122 = CAP-NP: Capacitor
U7 U9 = MT48LC16M16A2FG: 256Mb Synchronous High-Speed CMOS DRAM, 16Mb x 16Bit x 4 Banks, 54-Ball FPGA, Commercial
U8 = AM29LV640DU90RWHI: 64 Mb (4 M x 16) CMOS 3.0 Volt, Uniform Sector Flash Memory with VersatileI/O Control, 63-ball FBGA, Industrial Grade

## Sheet FPGA.SchDoc: Pin Swapping
size 863 x 558 mm; DocumentNumber: 4; SheetNumber: 4; SheetTotal: 6
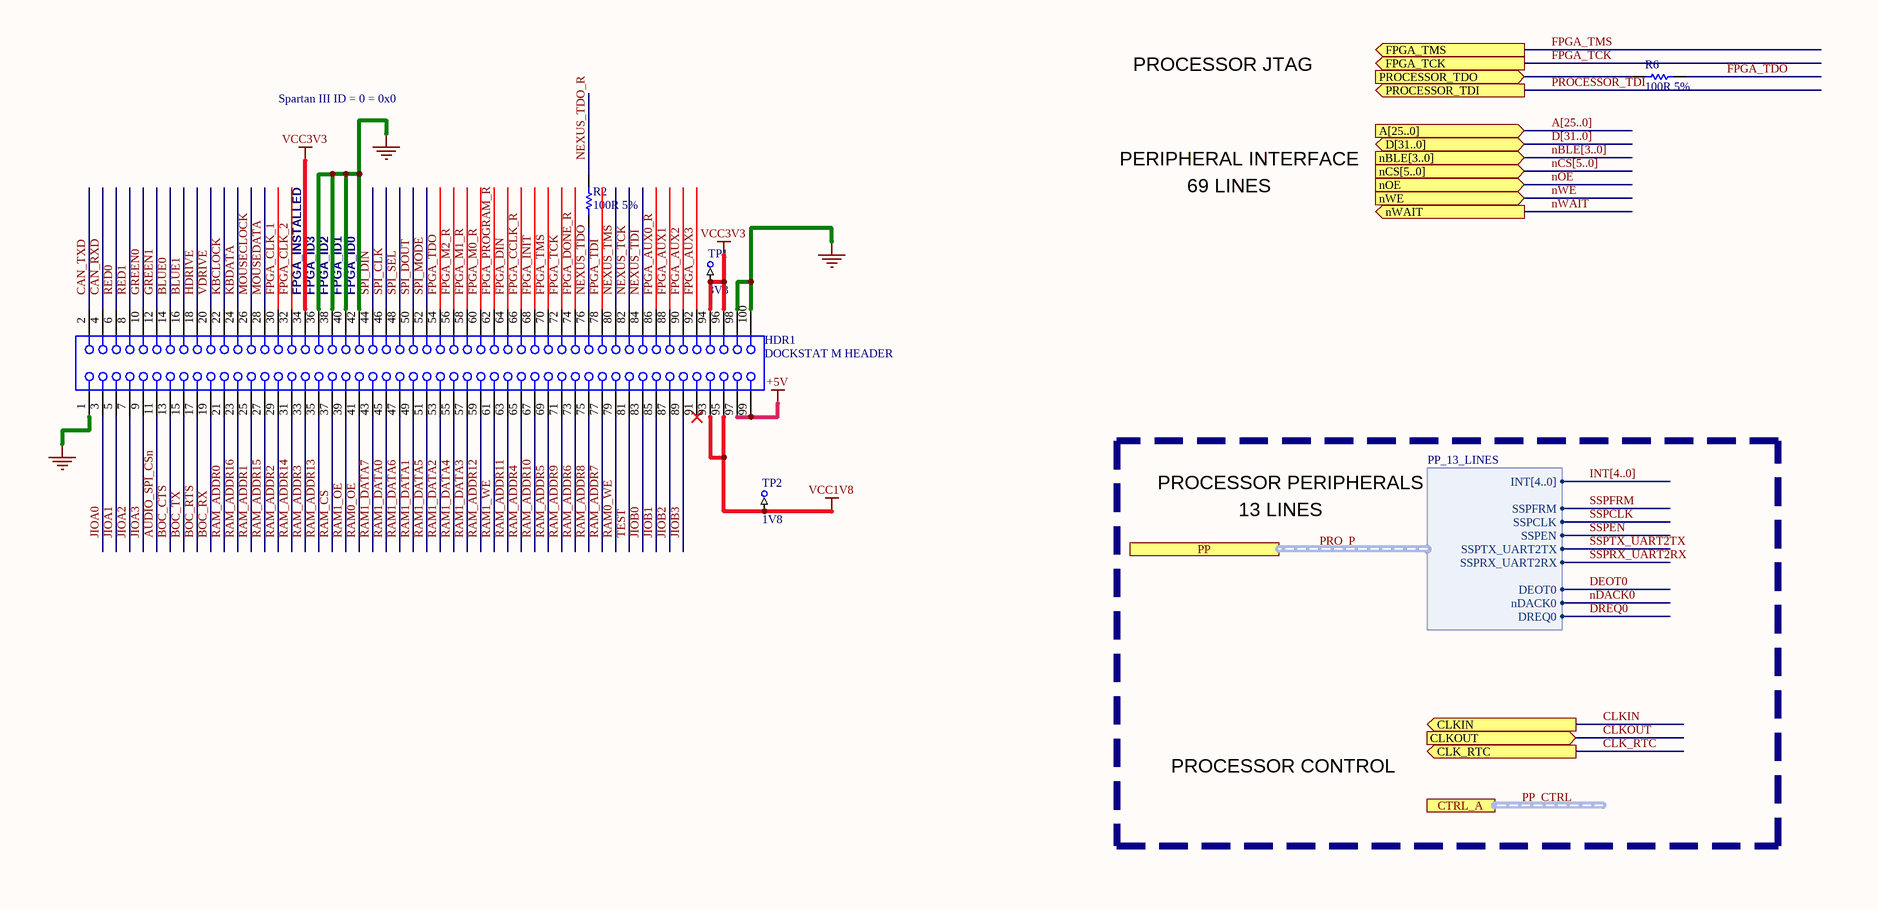
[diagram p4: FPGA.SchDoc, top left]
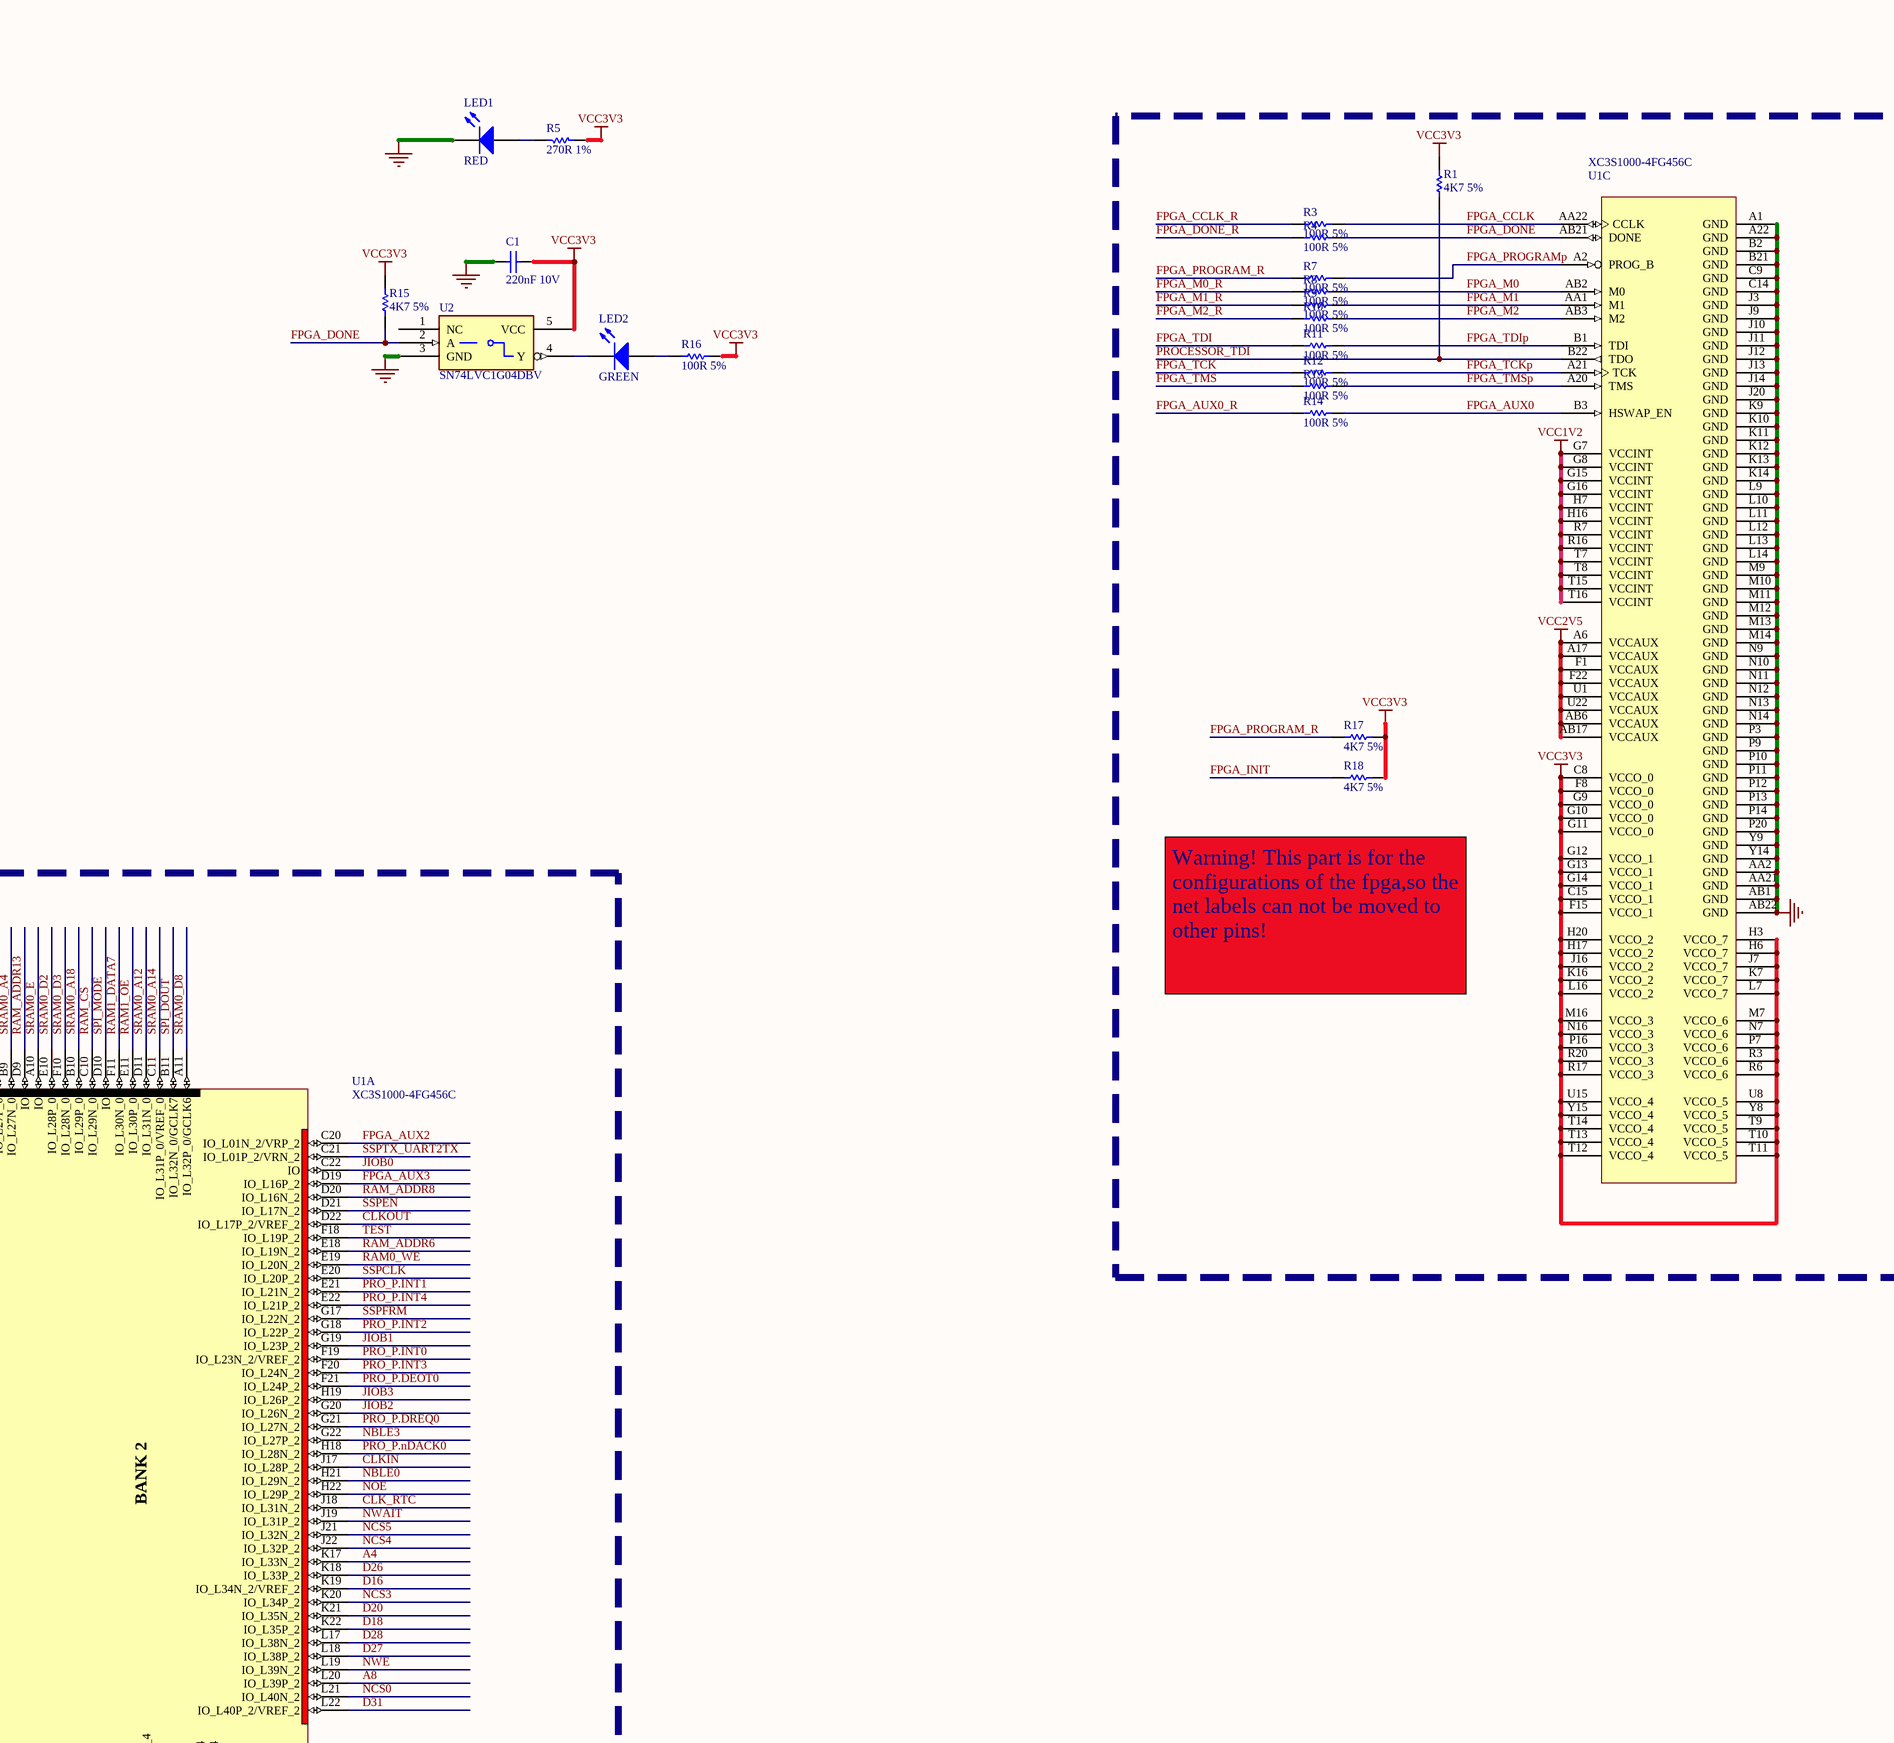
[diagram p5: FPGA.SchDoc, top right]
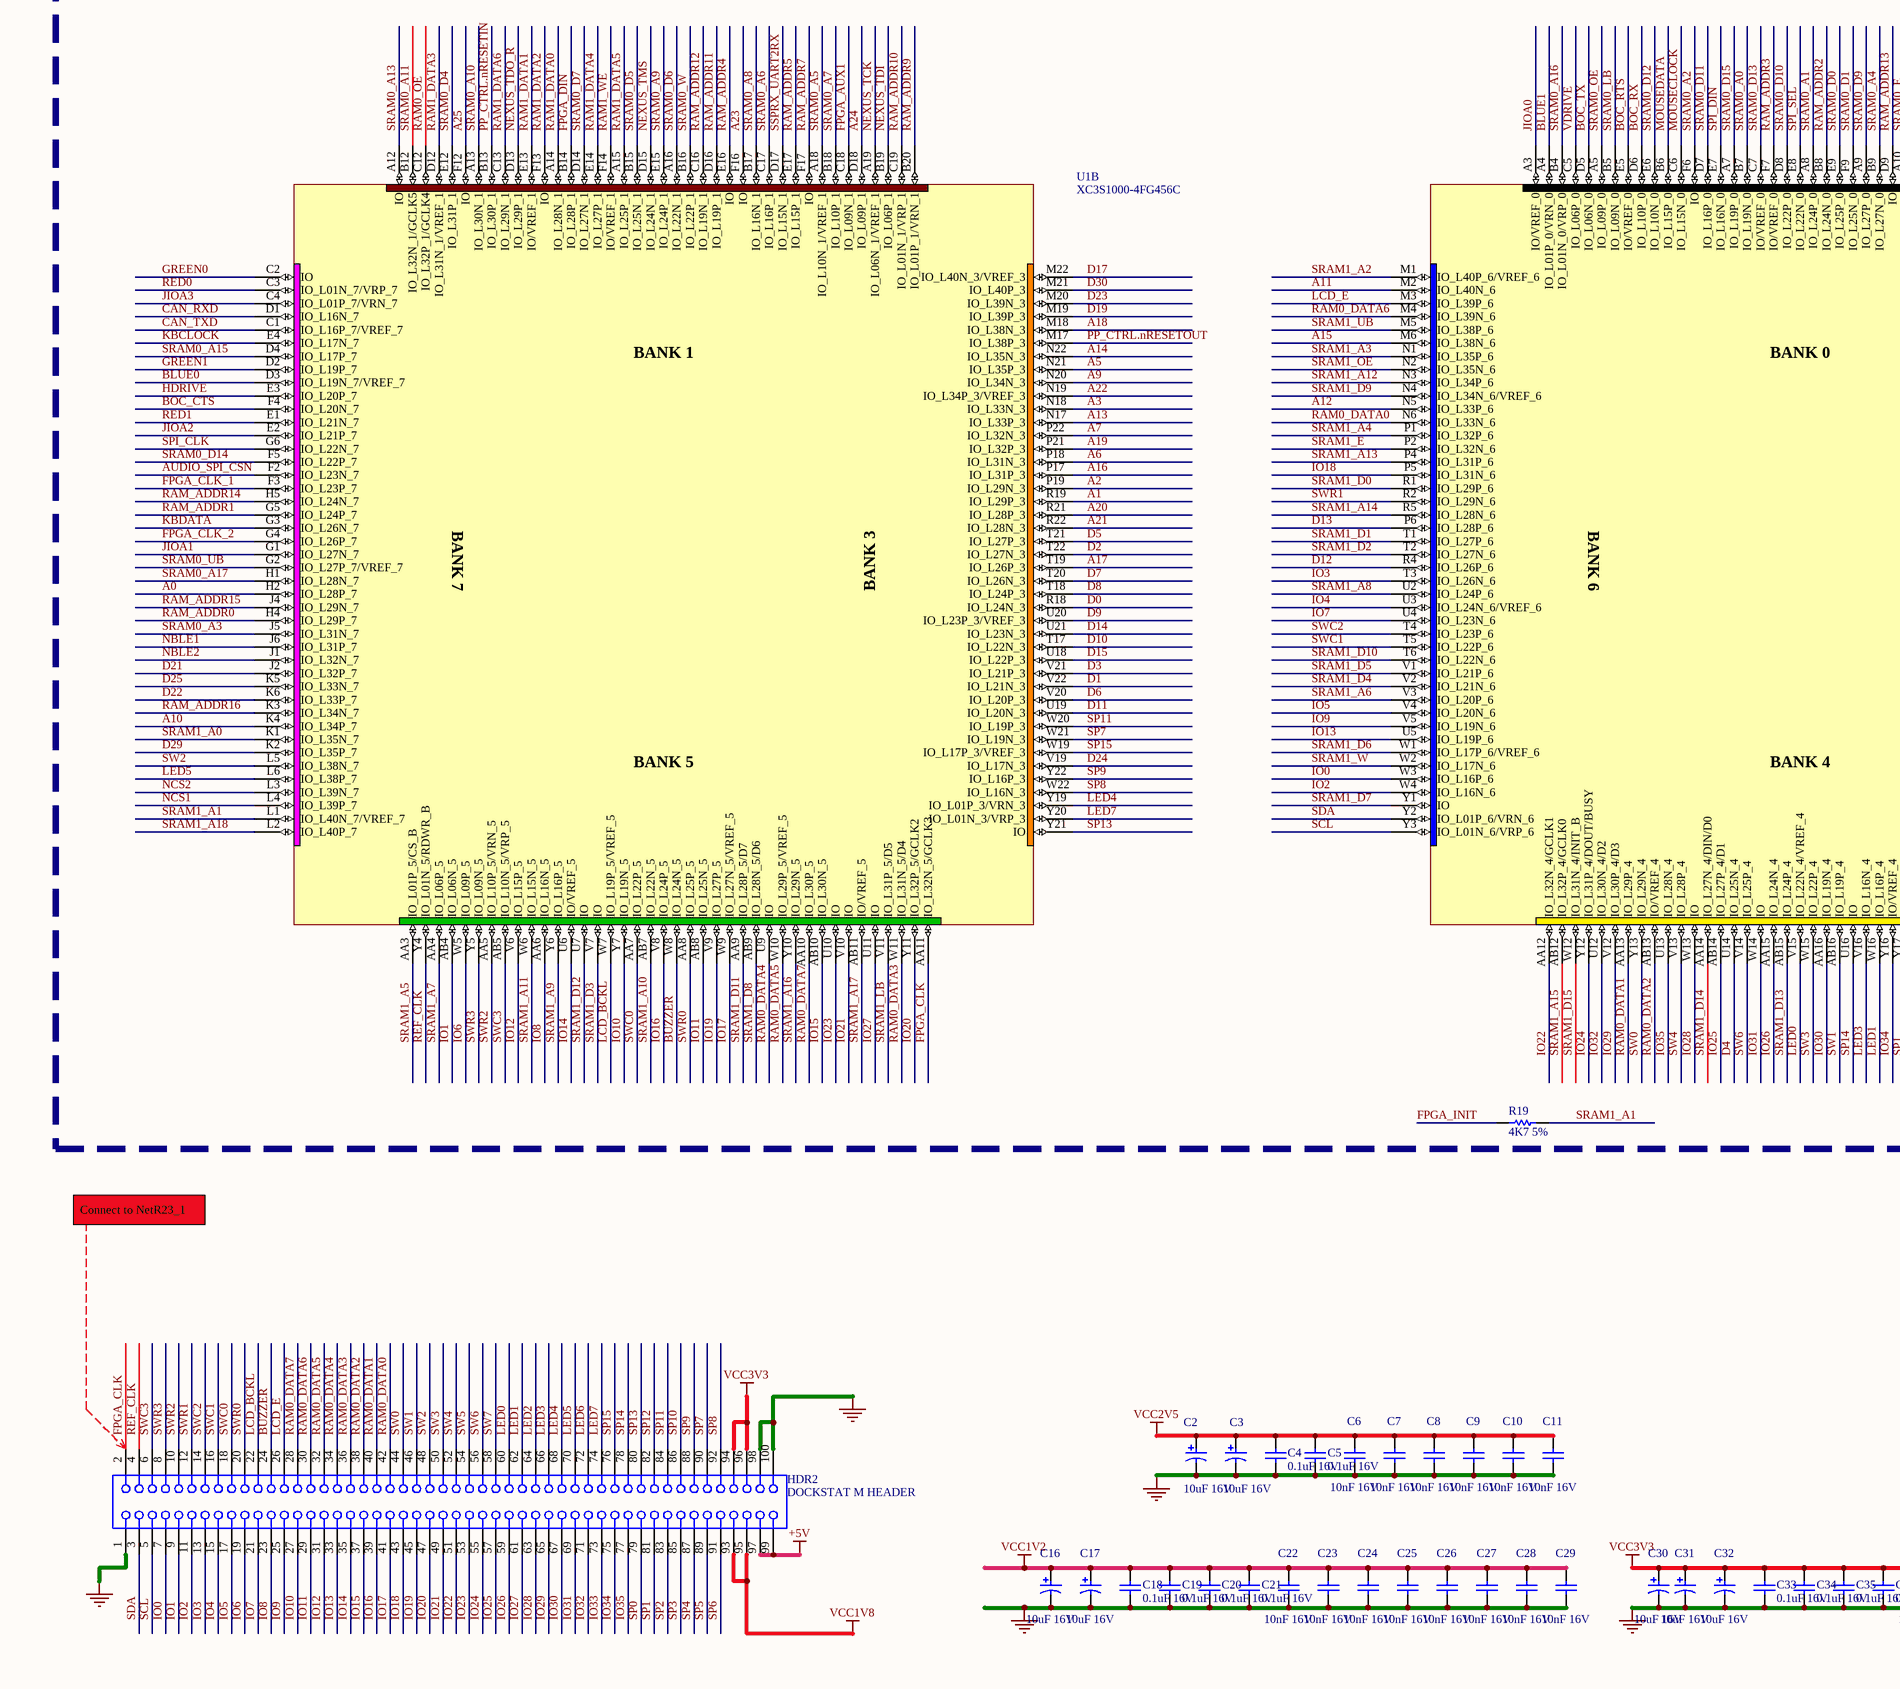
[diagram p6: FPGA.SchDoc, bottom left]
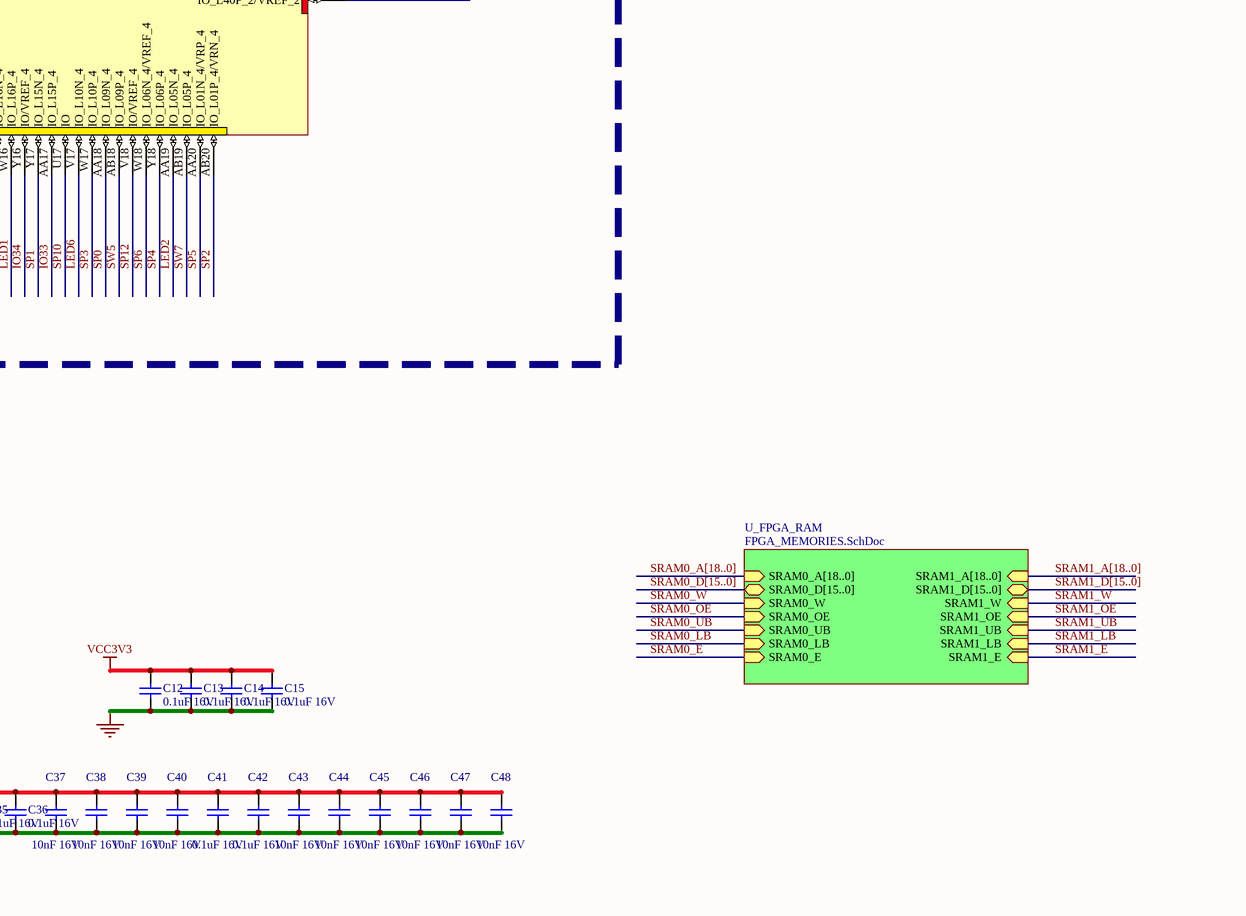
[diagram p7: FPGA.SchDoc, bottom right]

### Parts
C1  220nF 10V  [CAPC1608]
C2  10uF 16V  [CAPC3528]
C3  10uF 16V  [CAPC3528]
C4  0.1uF 16V  [CAPC1005]
C5  0.1uF 16V  [CAPC1005]
C6  10nF 16V  [CAPC1005]
C7  10nF 16V  [CAPC1005]
C8  10nF 16V  [CAPC1005]
C9  10nF 16V  [CAPC1005]
C10  10nF 16V  [CAPC1005]
C11  10nF 16V  [CAPC1005]
C12  0.1uF 16V  [CAPC1005]
C13  0.1uF 16V  [CAPC1005]
C14  0.1uF 16V  [CAPC1005]
C15  0.1uF 16V  [CAPC1005]
C16  10uF 16V  [CAPC3528]
C17  10uF 16V  [CAPC3528]
C18  0.1uF 16V  [CAPC1005]
C19  0.1uF 16V  [CAPC1005]
C20  0.1uF 16V  [CAPC1005]
C21  0.1uF 16V  [CAPC1005]
C22  10nF 16V  [CAPC1005]
C23  10nF 16V  [CAPC1005]
C24  10nF 16V  [CAPC1005]
C25  10nF 16V  [CAPC1005]
C26  10nF 16V  [CAPC1005]
C27  10nF 16V  [CAPC1005]
C28  10nF 16V  [CAPC1005]
C29  10nF 16V  [CAPC1005]
C30  10uF 16V  [CAPC3528]
C31  10uF 16V  [CAPC3528]
C32  10uF 16V  [CAPC3528]
C33  0.1uF 16V  [CAPC1005]
C34  0.1uF 16V  [CAPC1005]
C35  0.1uF 16V  [CAPC1005]
C36  0.1uF 16V  [CAPC1005]
C37  10nF 16V  [CAPC1005]
C38  10nF 16V  [CAPC1005]
C39  10nF 16V  [CAPC1005]
C40  10nF 16V  [CAPC1005]
C41  0.1uF 16V  [CAPC1005]
C42  0.1uF 16V  [CAPC1005]
C43  10nF 16V  [CAPC1005]
C44  10nF 16V  [CAPC1005]
C45  10nF 16V  [CAPC1005]
C46  10nF 16V  [CAPC1005]
C47  10nF 16V  [CAPC1005]
C48  10nF 16V  [CAPC1005]
HDR1  DOCKSTAT M HEADER  [54075]
HDR2  DOCKSTAT M HEADER  [54075]
LED1  RED  [LED2013]
LED2  GREEN  [LED2013]
R1  4K7 5%  [RESC1005]
R2  100R 5%  [RESC2012]
R3  100R 5%  [RESC2012]
R4  100R 5%  [RESC2012]
R5  270R 1%  [RESC2012]
R6  100R 5%  [RESC2012]
R7  100R 5%  [RESC2012]
R8  100R 5%  [RESC2012]
R9  100R 5%  [RESC2012]
R10  100R 5%  [RESC2012]
R11  100R 5%  [RESC2012]
R12  100R 5%  [RESC2012]
R13  100R 5%  [RESC2012]
R14  100R 5%  [RESC2012]
R15  4K7 5%  [RESC1005]
R16  100R 5%  [RESC2012]
R17  4K7 5%  [RESC1005]
R18  4K7 5%  [RESC1005]
R19  4K7 5%  [RESC1005]
TP1  3V3  [TestPin]  (no BOM)
TP2  1V8  [TestPin]  (no BOM)
U1  XC3S1000-4FG456C  [BGA100P22X22-456]  (parts A,B,C of 3)
U2  SN74LVC1G04DBV  [SOT95P280-5]

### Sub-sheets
U_FPGA_RAM = FPGA_MEMORIES.SchDoc: SRAM0_A[18..0] (in), SRAM0_D[15..0] (bidir), SRAM0_W (in), SRAM0_OE (in), SRAM0_UB (in), SRAM0_LB (in), SRAM0_E (in), SRAM1_A[18..0] (in), SRAM1_D[15..0] (bidir), SRAM1_W (in), SRAM1_OE (in), SRAM1_UB (in), SRAM1_LB (in), SRAM1_E (in)

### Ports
A[25..0] (in), CLK_RTC (out), CLKIN (out), CLKOUT (in), CTRL_A (harness P_C_HARNESS), D[31..0] (bidir), FPGA_TCK (out), FPGA_TMS (out), nBLE[3..0] (in), nCS[5..0] (in), nOE (in), nWAIT (out), nWE (in), PP (harness PP_13_LINES), PROCESSOR_TDI (out), PROCESSOR_TDO (in)

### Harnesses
PP_13_LINES: INT[4..0], SSPFRM, SSPCLK, SSPEN, SSPTX_UART2TX, SSPRX_UART2RX, DEOT0, nDACK0, DREQ0

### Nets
+5V: HDR1.97 HDR1.99 HDR2.97 HDR2.99
GND: C1.1 C2.2 C3.2 C4.2 C5.2 C6.2 C7.2 C8.2 C9.2 C10.2 C11.2 C12.2 C13.2 C14.2 C15.2 C16.2 C17.2 C18.2 C19.2 C20.2 C21.2 C22.2 C23.2 C24.2 C25.2 C26.2 C27.2 C28.2 C29.2 C30.2 C31.2 C32.2 C33.2 C34.2 C35.2 C36.2 C37.2 C38.2 C39.2 C40.2 C41.2 C42.2 C43.2 C44.2 C45.2 C46.2 C47.2 C48.2 HDR1.1 HDR1.36 HDR1.38 HDR1.40 HDR1.42 HDR1.98 HDR1.100 HDR2.1 HDR2.98 HDR2.100 LED1.2(K) U1.A1(GND) U1.A22(GND) U1.AA2(GND) U1.AA21(GND) U1.AB1(GND) U1.AB22(GND) U1.B2(GND) U1.B21(GND) U1.C9(GND) U1.C14(GND) U1.J3(GND) U1.J9(GND) U1.J10(GND) U1.J11(GND) U1.J12(GND) U1.J13(GND) U1.J14(GND) U1.J20(GND) U1.K9(GND) U1.K10(GND) U1.K11(GND) U1.K12(GND) U1.K13(GND) U1.K14(GND) U1.L9(GND) U1.L10(GND) U1.L11(GND) U1.L12(GND) U1.L13(GND) U1.L14(GND) U1.M9(GND) U1.M10(GND) U1.M11(GND) U1.M12(GND) U1.M13(GND) U1.M14(GND) U1.N9(GND) U1.N10(GND) U1.N11(GND) U1.N12(GND) U1.N13(GND) U1.N14(GND) U1.P3(GND) U1.P9(GND) U1.P10(GND) U1.P11(GND) U1.P12(GND) U1.P13(GND) U1.P14(GND) U1.P20(GND) U1.Y9(GND) U1.Y14(GND) U2.3(GND)
VCC1V2: C16.1 C17.1 C18.1 C19.1 C20.1 C21.1 C22.1 C23.1 C24.1 C25.1 C26.1 C27.1 C28.1 C29.1 U1.G7(VCCINT) U1.G8(VCCINT) U1.G15(VCCINT) U1.G16(VCCINT) U1.H7(VCCINT) U1.H16(VCCINT) U1.R7(VCCINT) U1.R16(VCCINT) U1.T7(VCCINT) U1.T8(VCCINT) U1.T15(VCCINT) U1.T16(VCCINT)
VCC1V8: HDR1.93 HDR1.95 HDR2.93 HDR2.95 TP2.1
VCC2V5: C2.1 C3.1 C4.1 C5.1 C6.1 C7.1 C8.1 C9.1 C10.1 C11.1 U1.A6(VCCAUX) U1.A17(VCCAUX) U1.AB6(VCCAUX) U1.AB17(VCCAUX) U1.F1(VCCAUX) U1.F22(VCCAUX) U1.U1(VCCAUX) U1.U22(VCCAUX)
VCC3V3: C1.2 C12.1 C13.1 C14.1 C15.1 C30.1 C31.1 C32.1 C33.1 C34.1 C35.1 C36.1 C37.1 C38.1 C39.1 C40.1 C41.1 C42.1 C43.1 C44.1 C45.1 C46.1 C47.1 C48.1 HDR1.34 HDR1.94 HDR1.96 HDR2.94 HDR2.96 R1.1 R5.1 R15.2 R16.2 R17.2 R18.2 TP1.1 U1.C8(VCCO_0) U1.C15(VCCO_1) U1.F8(VCCO_0) U1.F15(VCCO_1) U1.G9(VCCO_0) U1.G10(VCCO_0) U1.G11(VCCO_0) U1.G12(VCCO_1) U1.G13(VCCO_1) U1.G14(VCCO_1) U1.H3(VCCO_7) U1.H6(VCCO_7) U1.H17(VCCO_2) U1.H20(VCCO_2) U1.J7(VCCO_7) U1.J16(VCCO_2) U1.K7(VCCO_7) U1.K16(VCCO_2) U1.L7(VCCO_7) U1.L16(VCCO_2) U1.M7(VCCO_6) U1.M16(VCCO_3) U1.N7(VCCO_6) U1.N16(VCCO_3) U1.P7(VCCO_6) U1.P16(VCCO_3) U1.R3(VCCO_6) U1.R6(VCCO_6) U1.R17(VCCO_3) U1.R20(VCCO_3) U1.T9(VCCO_5) U1.T10(VCCO_5) U1.T11(VCCO_5) U1.T12(VCCO_4) U1.T13(VCCO_4) U1.T14(VCCO_4) U1.U8(VCCO_5) U1.U15(VCCO_4) U1.Y8(VCCO_5) U1.Y15(VCCO_4) U2.5(VCC)
A0: U1.H2(IO_L28P_7)
A1: U1.R19(IO_L29P_3)
A2: U1.P19(IO_L29N_3)
A3: U1.N18(IO_L33N_3)
A4: U1.K17(IO_L33N_2)
A5: U1.N21(IO_L35P_3)
A6: U1.P18(IO_L31N_3)
A7: U1.P22(IO_L32N_3)
A8: U1.L20(IO_L39P_2)
A9: U1.N20(IO_L34N_3)
A10: U1.K4(IO_L34P_7)
A11: U1.M2(IO_L40N_6)
A12: U1.N5(IO_L33P_6)
A13: U1.N17(IO_L33P_3)
A14: U1.N22(IO_L35N_3)
A15: U1.M6(IO_L38N_6)
A16: U1.P17(IO_L31P_3)
A17: U1.T19(IO_L26P_3)
A18: U1.M18(IO_L38N_3)
A19: U1.P21(IO_L32P_3)
A20: U1.R21(IO_L28P_3)
A21: U1.R22(IO_L28N_3)
A22: U1.N19(IO_L34P_3/VREF_3)
A23: U1.F16(IO)
A24: U1.D18(IO_L09P_1)
A25: U1.F12(IO)
AUDIO_SPI_CSn: HDR1.11 U1.F2(IO_L23N_7)
BLUE0: HDR1.14 U1.D3(IO_L19N_7/VREF_7)
BLUE1: HDR1.16 U1.A4(IO_L01P_0/VRN_0)
BOC_CTS: HDR1.13 U1.F4(IO_L20N_7)
BOC_RTS: HDR1.17 U1.E5(IO/VREF_0)
BOC_RX: HDR1.19 U1.D6(IO_L10P_0)
BOC_TX: HDR1.15 U1.D5(IO_L06N_0)
BUZZER: HDR2.24 U1.W8(IO_L24N_5)
CAN_RXD: HDR1.4 U1.D1(IO_L16N_7)
CAN_TXD: HDR1.2 U1.C1(IO_L16P_7/VREF_7)
CLK_RTC: U1.J18(IO_L31N_2) ; port CLK_RTC
CLKIN: U1.J17(IO_L28P_2) ; port CLKIN
CLKOUT: U1.D22(IO_L17P_2/VREF_2) ; port CLKOUT
D0: U1.R18(IO_L24N_3)
D1: U1.V22(IO_L21N_3)
D2: U1.T22(IO_L27N_3)
D3: U1.V21(IO_L21P_3)
D4: U1.U14(IO_L25N_4)
D5: U1.T21(IO_L27P_3)
D6: U1.V20(IO_L20P_3)
D7: U1.T20(IO_L26N_3)
D8: U1.T18(IO_L24P_3)
D9: U1.U20(IO_L23P_3/VREF_3)
D10: U1.T17(IO_L22N_3)
D11: U1.U19(IO_L20N_3)
D12: U1.R4(IO_L26P_6)
D13: U1.P6(IO_L28P_6)
D14: U1.U21(IO_L23N_3)
D15: U1.U18(IO_L22P_3)
D16: U1.K19(IO_L34N_2/VREF_2)
D17: U1.M22(IO_L40N_3/VREF_3)
D18: U1.K22(IO_L35P_2)
D19: U1.M19(IO_L39P_3)
D20: U1.K21(IO_L35N_2)
D21: U1.J2(IO_L32P_7)
D22: U1.K6(IO_L33P_7)
D23: U1.M20(IO_L39N_3)
D24: U1.V19(IO_L17N_3)
D25: U1.K5(IO_L33N_7)
D26: U1.K18(IO_L33P_2)
D27: U1.L18(IO_L38P_2)
D28: U1.L17(IO_L38N_2)
D29: U1.K2(IO_L35P_7)
D30: U1.M21(IO_L40P_3)
D31: U1.L22(IO_L40P_2/VREF_2)
FPGA_AUX0: R14.1 U1.B3(HSWAP_EN)
FPGA_AUX0_R: HDR1.86 R14.2
FPGA_AUX1: HDR1.88 U1.C18(IO_L09N_1)
FPGA_AUX2: HDR1.90 U1.C20(IO_L01N_2/VRP_2)
FPGA_AUX3: HDR1.92 U1.D19(IO_L16P_2)
FPGA_CCLK: R3.2 U1.AA22(CCLK)
FPGA_CCLK_R: HDR1.66 R3.1
FPGA_CLK: HDR2.2 U1.AA11(IO_L32N_5/GCLK3)
FPGA_CLK_1: HDR1.30 U1.F3(IO_L23P_7)
FPGA_CLK_2: HDR1.32 U1.G4(IO_L26P_7)
FPGA_DIN: HDR1.64 U1.B14(IO_L28P_1)
FPGA_DONE: R4.2 R15.1 U1.AB21(DONE) U2.2(A)
FPGA_DONE_R: HDR1.74 R4.1
FPGA_INIT: HDR1.68 R18.1 R19.1
FPGA_M0: R8.2 U1.AB2(M0)
FPGA_M0_R: HDR1.60 R8.1
FPGA_M1: R9.2 U1.AA1(M1)
FPGA_M1_R: HDR1.58 R9.1
FPGA_M2: R10.2 U1.AB3(M2)
FPGA_M2_R: HDR1.56 R10.1
FPGA_PROGRAM_R: HDR1.62 R7.1 R17.1
FPGA_PROGRAMp: R7.2 U1.A2(PROG_B)
FPGA_TCK: HDR1.72 R12.1 ; port FPGA_TCK
FPGA_TCKp: R12.2 U1.A21(TCK)
FPGA_TDI: HDR1.78 R11.1
FPGA_TDIp: R11.2 U1.B1(TDI)
FPGA_TDO: HDR1.54 R6.2
FPGA_TMS: HDR1.70 R13.1 ; port FPGA_TMS
FPGA_TMSp: R13.2 U1.A20(TMS)
GREEN0: HDR1.10 U1.C2(IO)
GREEN1: HDR1.12 U1.D2(IO_L19P_7)
HDRIVE: HDR1.18 U1.E3(IO_L20P_7)
IO0: HDR2.7 U1.W3(IO_L16P_6)
IO1: HDR2.9 U1.AB4(IO_L06N_5)
IO2: HDR2.11 U1.W4(IO_L16N_6)
IO3: HDR2.13 U1.T3(IO_L26N_6)
IO4: HDR2.15 U1.U3(IO_L24N_6/VREF_6)
IO5: HDR2.17 U1.V4(IO_L20N_6)
IO6: HDR2.19 U1.W5(IO_L09P_5)
IO7: HDR2.21 U1.U4(IO_L23N_6)
IO8: HDR2.23 U1.AA6(IO_L16N_5)
IO9: HDR2.25 U1.V5(IO_L19N_6)
IO10: HDR2.27 U1.Y7(IO_L19N_5)
IO11: HDR2.29 U1.AB8(IO_L25N_5)
IO12: HDR2.31 U1.V6(IO_L15P_5)
IO13: HDR2.33 U1.U5(IO_L19P_6)
IO14: HDR2.35 U1.U6(IO/VREF_5)
IO15: HDR2.37 U1.AB10(IO_L30N_5)
IO16: HDR2.39 U1.V8(IO_L24P_5)
IO17: HDR2.41 U1.W9(IO_L27N_5/VREF_5)
IO18: HDR2.43 U1.P5(IO_L31N_6)
IO19: HDR2.45 U1.V9(IO_L27P_5)
IO20: HDR2.47 U1.Y11(IO_L32P_5/GCLK2)
IO21: HDR2.49 U1.V10(IO)
IO22: HDR2.51 U1.AA12(IO_L32N_4/GCLK1)
IO23: HDR2.53 U1.U10(IO)
IO24: HDR2.55 U1.Y12(IO_L31P_4/DOUT/BUSY)
IO25: HDR2.57 U1.AB14(IO_L27P_4/D1)
IO26: HDR2.59 U1.AA15(IO_L24N_4)
IO27: HDR2.61 U1.U11(IO)
IO28: HDR2.63 U1.W13(IO)
IO29: HDR2.65 U1.V12(IO_L30P_4/D3)
IO30: HDR2.67 U1.AA16(IO_L19N_4)
IO31: HDR2.69 U1.W14(IO)
IO32: HDR2.71 U1.U12(IO_L30N_4/D2)
IO33: HDR2.73 U1.AA17(IO_L15P_4)
IO34: HDR2.75 U1.Y16(IO/VREF_4)
IO35: HDR2.77 U1.U13(IO_L28N_4)
JIOA0: HDR1.3 U1.A3(IO/VREF_0)
JIOA1: HDR1.5 U1.G1(IO_L27N_7)
JIOA2: HDR1.7 U1.E2(IO_L21P_7)
JIOA3: HDR1.9 U1.C4(IO_L01P_7/VRN_7)
JIOB0: HDR1.83 U1.C22(IO)
JIOB1: HDR1.85 U1.G19(IO_L23P_2)
JIOB2: HDR1.87 U1.G20(IO_L26N_2)
JIOB3: HDR1.89 U1.H19(IO_L26P_2)
KBCLOCK: HDR1.22 U1.E4(IO_L17N_7)
KBDATA: HDR1.24 U1.G3(IO_L26N_7)
LCD_BCKL: HDR2.22 U1.W7(IO_L19P_5/VREF_5)
LCD_E: HDR2.26 U1.M3(IO_L39P_6)
LED0: HDR2.60 U1.V15(IO_L22N_4/VREF_4)
LED1: HDR2.62 U1.W16(IO_L16P_4)
LED2: HDR2.64 U1.AA19(IO_L05N_4)
LED3: HDR2.66 U1.V16(IO_L16N_4)
LED4: HDR2.68 U1.Y19(IO_L01P_3/VRN_3)
LED5: HDR2.70 U1.L6(IO_L38P_7)
LED6: HDR2.72 U1.V17(IO_L10N_4)
LED7: HDR2.74 U1.Y20(IO_L01N_3/VRP_3)
MOUSECLOCK: HDR1.26 U1.C6(IO_L15N_0)
MOUSEDATA: HDR1.28 U1.B6(IO_L15P_0)
nBLE0: U1.H21(IO_L29N_2)
nBLE1: U1.J6(IO_L31P_7)
nBLE2: U1.J1(IO_L32N_7)
nBLE3: U1.G22(IO_L27P_2)
nCS0: U1.L21(IO_L40N_2)
nCS1: U1.L4(IO_L39P_7)
nCS2: U1.L3(IO_L39N_7)
nCS3: U1.K20(IO_L34P_2)
nCS4: U1.J22(IO_L32P_2)
nCS5: U1.J21(IO_L32N_2)
NEXUS_TCK: HDR1.82 U1.A19(IO_L06N_1/VREF_1)
NEXUS_TDI: HDR1.84 U1.B19(IO_L06P_1)
NEXUS_TDO: HDR1.76 R2.1
NEXUS_TDO_R: R2.2 U1.D13(IO_L29P_1)
NEXUS_TMS: HDR1.80 U1.D15(IO_L24N_1)
nOE: U1.H22(IO_L29P_2) ; port nOE
nWAIT: U1.J19(IO_L31P_2) ; port nWAIT
nWE: U1.L19(IO_L39N_2) ; port nWE
PP_CTRL.nRESETIN: U1.B13(IO_L30P_1)
PP_CTRL.nRESETOUT: U1.M17(IO_L38P_3)
PRO_P.DEOT0: U1.F21(IO_L24P_2)
PRO_P.DREQ0: U1.G21(IO_L27N_2)
PRO_P.INT0: U1.F19(IO_L23N_2/VREF_2)
PRO_P.INT1: U1.E21(IO_L21N_2)
PRO_P.INT2: U1.G18(IO_L22P_2)
PRO_P.INT3: U1.F20(IO_L24N_2)
PRO_P.INT4: U1.E22(IO_L21P_2)
PRO_P.nDACK0: U1.H18(IO_L28N_2)
PROCESSOR_TDI: R1.2 U1.B22(TDO) ; port PROCESSOR_TDI
PROCESSOR_TDO: R6.1 ; port PROCESSOR_TDO
RAM0_DATA0: HDR2.42 U1.N6(IO_L33N_6)
RAM0_DATA1: HDR2.40 U1.AA13(IO_L29P_4)
RAM0_DATA2: HDR2.38 U1.AB13(IO/VREF_4)
RAM0_DATA3: HDR2.36 U1.W11(IO_L31N_5/D4)
RAM0_DATA4: HDR2.34 U1.U9(IO)
RAM0_DATA5: HDR2.32 U1.W10(IO_L29P_5/VREF_5)
RAM0_DATA6: HDR2.30 U1.M4(IO_L39N_6)
RAM0_DATA7: HDR2.28 U1.AA10(IO_L30P_5)
RAM0_OE: HDR1.41 U1.C12(IO_L32P_1/GCLK4)
RAM0_WE: HDR1.79 U1.E19(IO_L20N_2)
RAM1_DATA0: HDR1.45 U1.A14(IO_L28N_1)
RAM1_DATA1: HDR1.49 U1.E13(IO/VREF_1)
RAM1_DATA2: HDR1.53 U1.F13(IO)
RAM1_DATA3: HDR1.57 U1.D12(IO_L31N_1/VREF_1)
RAM1_DATA4: HDR1.55 U1.E14(IO_L27P_1)
RAM1_DATA5: HDR1.51 U1.A15(IO_L25P_1)
RAM1_DATA6: HDR1.47 U1.C13(IO_L29N_1)
RAM1_DATA7: HDR1.43 U1.F11(IO_L30N_0)
RAM1_OE: HDR1.39 U1.E11(IO_L30P_0)
RAM1_WE: HDR1.61 U1.F14(IO/VREF_1)
RAM_ADDR0: HDR1.21 U1.H4(IO_L29P_7)
RAM_ADDR1: HDR1.25 U1.G5(IO_L24P_7)
RAM_ADDR2: HDR1.29 U1.B8(IO_L24N_0)
RAM_ADDR3: HDR1.33 U1.F7(IO/VREF_0)
RAM_ADDR4: HDR1.65 U1.E16(IO)
RAM_ADDR5: HDR1.69 U1.E17(IO_L15P_1)
RAM_ADDR6: HDR1.73 U1.E18(IO_L19N_2)
RAM_ADDR7: HDR1.77 U1.F17(IO)
RAM_ADDR8: HDR1.75 U1.D20(IO_L16N_2)
RAM_ADDR9: HDR1.71 U1.B20(IO_L01P_1/VRN_1)
RAM_ADDR10: HDR1.67 U1.C19(IO_L01N_1/VRP_1)
RAM_ADDR11: HDR1.63 U1.D16(IO_L19P_1)
RAM_ADDR12: HDR1.59 U1.C16(IO_L19N_1)
RAM_ADDR13: HDR1.35 U1.D9(IO)
RAM_ADDR14: HDR1.31 U1.H5(IO_L24N_7)
RAM_ADDR15: HDR1.27 U1.J4(IO_L29N_7)
RAM_ADDR16: HDR1.23 U1.K3(IO_L34N_7)
RAM_CS: HDR1.37 U1.C10(IO_L29N_0)
RED0: HDR1.6 U1.C3(IO_L01N_7/VRP_7)
RED1: HDR1.8 U1.E1(IO_L21N_7)
REF_CLK: HDR2.4 U1.Y4(IO_L01N_5/RDWR_B)
SCL: HDR2.5 U1.Y3(IO_L01N_6/VRP_6)
SDA: HDR2.3 U1.Y2(IO_L01P_6/VRN_6)
SP0: HDR2.79 U1.AA18(IO_L09N_4)
SP1: HDR2.81 U1.Y17(IO_L15N_4)
SP2: HDR2.83 U1.AB20(IO_L01P_4/VRN_4)
SP3: HDR2.85 U1.W17(IO_L10P_4)
SP4: HDR2.87 U1.Y18(IO_L06P_4)
SP5: HDR2.89 U1.AA20(IO_L01N_4/VRP_4)
SP6: HDR2.91 U1.W18(IO_L06N_4/VREF_4)
SP7: HDR2.90 U1.W21(IO_L19N_3)
SP8: HDR2.92 U1.W22(IO_L16N_3)
SP9: HDR2.88 U1.Y22(IO_L16P_3)
SP10: HDR2.86 U1.U17(IO)
SP11: HDR2.84 U1.W20(IO_L19P_3)
SP12: HDR2.82 U1.V18(IO/VREF_4)
SP13: HDR2.80 U1.Y21(IO)
SP14: HDR2.78 U1.U16(IO)
SP15: HDR2.76 U1.W19(IO_L17P_3/VREF_3)
SPI_CLK: HDR1.46 U1.G6(IO_L22N_7)
SPI_DIN: HDR1.44 U1.E7(IO_L16N_0)
SPI_DOUT: HDR1.50 U1.B11(IO_L32N_0/GCLK7)
SPI_MODE: HDR1.52 U1.D10(IO)
SPI_SEL: HDR1.48 U1.E8(IO_L22N_0)
SRAM0_A0: U1.B7(IO_L19N_0)
SRAM0_A1: U1.A8(IO_L24P_0)
SRAM0_A2: U1.F6(IO)
SRAM0_A3: U1.J5(IO_L31N_7)
SRAM0_A4: U1.B9(IO_L27N_0)
SRAM0_A5: U1.A18(IO_L10N_1/VREF_1)
SRAM0_A6: U1.C17(IO_L16P_1)
SRAM0_A7: U1.B18(IO_L10P_1)
SRAM0_A8: U1.B17(IO_L16N_1)
SRAM0_A9: U1.E15(IO_L24P_1)
SRAM0_A10: U1.A13(IO_L30N_1)
SRAM0_A11: U1.B12(IO_L32N_1/GCLK5)
SRAM0_A12: U1.D11(IO_L31N_0)
SRAM0_A13: U1.A12(IO)
SRAM0_A14: U1.C11(IO_L31P_0/VREF_0)
SRAM0_A15: U1.D4(IO_L17P_7)
SRAM0_A16: U1.B4(IO_L01N_0/VRP_0)
SRAM0_A17: U1.H1(IO_L28N_7)
SRAM0_A18: U1.B10(IO_L29P_0)
SRAM0_D0: U1.E9(IO_L25P_0)
SRAM0_D1: U1.F9(IO_L25N_0)
SRAM0_D2: U1.E10(IO_L28P_0)
SRAM0_D3: U1.F10(IO_L28N_0)
SRAM0_D4: U1.E12(IO_L31P_1)
SRAM0_D5: U1.B15(IO_L25N_1)
SRAM0_D6: U1.A16(IO_L22N_1)
SRAM0_D7: U1.D14(IO_L27N_1)
SRAM0_D8: U1.A11(IO_L32P_0/GCLK6)
SRAM0_D9: U1.A9(IO_L27P_0)
SRAM0_D10: U1.D8(IO_L22P_0)
SRAM0_D11: U1.D7(IO_L16P_0)
SRAM0_D12: U1.E6(IO_L10N_0)
SRAM0_D13: U1.C7(IO/VREF_0)
SRAM0_D14: U1.F5(IO_L22P_7)
SRAM0_D15: U1.A7(IO_L19P_0)
SRAM0_E: U1.A10(IO) ; sheet U_FPGA_RAM/SRAM0_E
SRAM0_LB: U1.B5(IO_L09N_0) ; sheet U_FPGA_RAM/SRAM0_LB
SRAM0_OE: U1.A5(IO_L09P_0) ; sheet U_FPGA_RAM/SRAM0_OE
SRAM0_UB: U1.G2(IO_L27P_7/VREF_7) ; sheet U_FPGA_RAM/SRAM0_UB
SRAM0_W: U1.B16(IO_L22P_1) ; sheet U_FPGA_RAM/SRAM0_W
SRAM1_A0: U1.K1(IO_L35N_7)
SRAM1_A1: R19.2 U1.L1(IO_L40N_7/VREF_7)
SRAM1_A2: U1.M1(IO_L40P_6/VREF_6)
SRAM1_A3: U1.N1(IO_L35P_6)
SRAM1_A4: U1.P1(IO_L32P_6)
SRAM1_A5: U1.AA3(IO_L01P_5/CS_B)
SRAM1_A6: U1.V3(IO_L20P_6)
SRAM1_A7: U1.AA4(IO_L06P_5)
SRAM1_A8: U1.U2(IO_L24P_6)
SRAM1_A9: U1.Y6(IO_L16P_5)
SRAM1_A10: U1.AB7(IO_L22N_5)
SRAM1_A11: U1.W6(IO_L15N_5)
SRAM1_A12: U1.N3(IO_L34P_6)
SRAM1_A13: U1.P4(IO_L31P_6)
SRAM1_A14: U1.R5(IO_L28N_6)
SRAM1_A15: U1.AB12(IO_L32P_4/GCLK0)
SRAM1_A16: U1.Y10(IO_L29N_5)
SRAM1_A17: U1.AB11(IO/VREF_5)
SRAM1_A18: U1.L2(IO_L40P_7)
SRAM1_D0: U1.R1(IO_L29P_6)
SRAM1_D1: U1.T1(IO_L27P_6)
SRAM1_D2: U1.T2(IO_L27N_6)
SRAM1_D3: U1.V7(IO)
SRAM1_D4: U1.V2(IO_L21N_6)
SRAM1_D5: U1.V1(IO_L21P_6)
SRAM1_D6: U1.W1(IO_L17P_6/VREF_6)
SRAM1_D7: U1.Y1(IO)
SRAM1_D8: U1.AB9(IO_L28N_5/D6)
SRAM1_D9: U1.N4(IO_L34N_6/VREF_6)
SRAM1_D10: U1.T6(IO_L22N_6)
SRAM1_D11: U1.AA9(IO_L28P_5/D7)
SRAM1_D12: U1.U7(IO)
SRAM1_D13: U1.AB15(IO_L24P_4)
SRAM1_D14: U1.AA14(IO_L27N_4/DIN/D0)
SRAM1_D15: U1.W12(IO_L31N_4/INIT_B)
SRAM1_E: U1.P2(IO_L32N_6) ; sheet U_FPGA_RAM/SRAM1_E
SRAM1_LB: U1.V11(IO_L31P_5/D5) ; sheet U_FPGA_RAM/SRAM1_LB
SRAM1_OE: U1.N2(IO_L35N_6) ; sheet U_FPGA_RAM/SRAM1_OE
SRAM1_UB: U1.M5(IO_L38P_6) ; sheet U_FPGA_RAM/SRAM1_UB
SRAM1_W: U1.W2(IO_L17N_6) ; sheet U_FPGA_RAM/SRAM1_W
SSPCLK: U1.E20(IO_L20P_2) ; port PP.SSPCLK  [project net PRO_P.SSPCLK]
SSPEN: U1.D21(IO_L17N_2) ; port PP.SSPEN  [project net PRO_P.SSPEN]
SSPFRM: U1.G17(IO_L22N_2) ; port PP.SSPFRM  [project net PRO_P.SSPFRM]
SSPRX_UART2RX: U1.D17(IO_L15N_1) ; port PP.SSPRX_UART2RX  [project net PRO_P.SSPRX_UART2RX]
SSPTX_UART2TX: U1.C21(IO_L01P_2/VRN_2) ; port PP.SSPTX_UART2TX  [project net PRO_P.SSPTX_UART2TX]
SW0: HDR2.44 U1.Y13(IO_L29N_4)
SW1: HDR2.46 U1.AB16(IO_L19P_4)
SW2: HDR2.48 U1.L5(IO_L38N_7)
SW3: HDR2.50 U1.W15(IO_L22P_4)
SW4: HDR2.52 U1.V13(IO_L28P_4)
SW5: HDR2.54 U1.AB18(IO_L09P_4)
SW6: HDR2.56 U1.V14(IO_L25P_4)
SW7: HDR2.58 U1.AB19(IO_L05P_4)
SWC0: HDR2.18 U1.AA7(IO_L22P_5)
SWC1: HDR2.16 U1.T5(IO_L22P_6)
SWC2: HDR2.14 U1.T4(IO_L23P_6)
SWC3: HDR2.6 U1.AB5(IO_L10N_5/VRP_5)
SWR0: HDR2.20 U1.AA8(IO_L25P_5)
SWR1: HDR2.12 U1.R2(IO_L29N_6)
SWR2: HDR2.10 U1.AA5(IO_L10P_5/VRN_5)
SWR3: HDR2.8 U1.Y5(IO_L09N_5)
TEST: HDR1.81 U1.F18(IO_L19P_2)
VDRIVE: HDR1.20 U1.C5(IO_L06P_0)
NetLED1_1: LED1.1(A) R5.2
NetLED2_1: LED2.1(A) R16.1
NetLED2_2: LED2.2(K) U2.4(Y)

Not connected (* = marked no-connect by the designer): HDR1 91*; U2 1(NC)

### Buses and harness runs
bus A[25..0] = port A[25..0]
bus D[31..0] = port D[31..0]
bus INT[4..0]
bus nBLE[3..0] = port nBLE[3..0]
bus nCS[5..0] = port nCS[5..0]
bus SRAM0_A[18..0] = sheet U_FPGA_RAM/SRAM0_A[18..0]
bus SRAM0_D[15..0] = sheet U_FPGA_RAM/SRAM0_D[15..0]
bus SRAM1_A[18..0] = sheet U_FPGA_RAM/SRAM1_A[18..0]
bus SRAM1_D[15..0] = sheet U_FPGA_RAM/SRAM1_D[15..0]
harness PP_CTRL = port CTRL_A
harness PRO_P = port PP

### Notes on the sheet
- PROCESSOR JTAG
- Spartan III ID = 0 = 0x0
- PERIPHERAL INTERFACE
- 69 LINES
- (near HDR1) FPGA_INSTALLED
- (near HDR1) FPGA_ID3
- (near HDR1) FPGA_ID2
- (near HDR1) FPGA_ID1
- (near HDR1) FPGA_ID0
- PROCESSOR PERIPHERALS
- 13 LINES
- PROCESSOR CONTROL
- Warning! This part is for the configurations of the fpga,so the net labels can not be moved to other pins!
- Connect to NetR23_1

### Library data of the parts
C1 = CAP-NP-220nF-10V-0603: Capacitor
C2 C3 C16 C17 C30-C32 = CAP-P-10uF-16V-MCCT-B: Polar Capacitor
C4 C5 C12-C15 C18-C21 C33-C36 C41 C42 = CAP-NP-0.1uF-16V-0402: Capacitor
C6-C11 C22-C29 C37-C40 C43-C48 = CAP-NP-10nF-16V-0402: Capacitor
HDR1 HDR2 = CON-DOCKSTAT-M-0.8mm: Board-to-Board, Docking Station, 0.80mm (.031") Pitch, Shielded Receptacle, Vertical, Ultra Low Profile, SMT
LED1 = LED-RED-HSMHC170: Typical GREEN SMD LED Agilent make
LED2 = LED-GRN-HSMHC170: Typical GREEN SMD LED Agilent make
R1 R15 R17-R19 = RES-4K7-0402: Resistor
R2-R4 R6-R14 R16 = RES-100R-0805: Resistor
R5 = RES-270R-1%-0805: Resistor
TP1 TP2 = TestPin
U1 = XC3S1000-4FG456C: Spartan-3 1.2V FPGA, 333 User I/Os, 456-ball FBGA, Standard Performance, Commercial Grade

## Sheet FPGA_MEMORIES.SchDoc: Pin Swapping
size 431 x 279 mm; DocumentNumber: 5; SheetNumber: 5; SheetTotal: 5
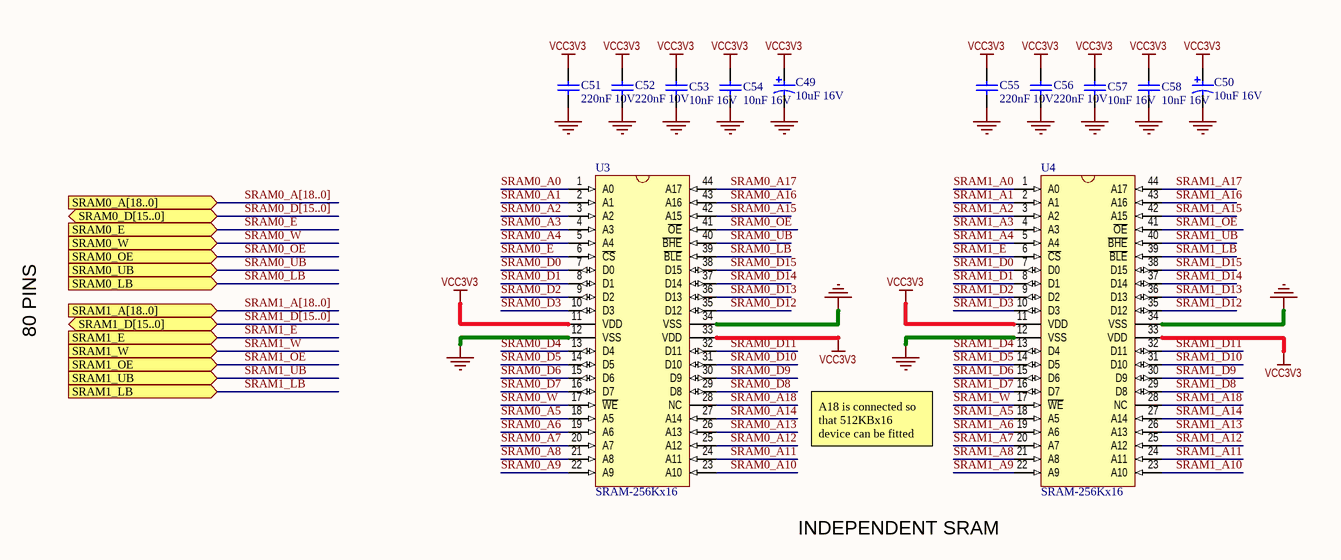
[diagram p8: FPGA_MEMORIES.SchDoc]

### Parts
C49  10uF 16V  [CAPC3528]
C50  10uF 16V  [CAPC3528]
C51  220nF 10V  [CAPC1608]
C52  220nF 10V  [CAPC1608]
C53  10nF 16V  [CAPC1005]
C54  10nF 16V  [CAPC1005]
C55  220nF 10V  [CAPC1608]
C56  220nF 10V  [CAPC1608]
C57  10nF 16V  [CAPC1005]
C58  10nF 16V  [CAPC1005]
U3  SRAM-256Kx16  [TSOP80P1176-44]
U4  SRAM-256Kx16  [TSOP80P1176-44]

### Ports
SRAM0_A[18..0] (in), SRAM0_D[15..0] (bidir), SRAM0_E (in), SRAM0_LB (in), SRAM0_OE (in), SRAM0_UB (in), SRAM0_W (in), SRAM1_A[18..0] (in), SRAM1_D[15..0] (bidir), SRAM1_E (in), SRAM1_LB (in), SRAM1_OE (in), SRAM1_UB (in), SRAM1_W (in)

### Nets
GND: C49.2 C50.2 C51.2 C52.2 C53.2 C54.2 C55.2 C56.2 C57.2 C58.2 U3.12(VSS) U3.34(VSS) U4.12(VSS) U4.34(VSS)
VCC3V3: C49.1 C50.1 C51.1 C52.1 C53.1 C54.1 C55.1 C56.1 C57.1 C58.1 U3.11(VDD) U3.33(VDD) U4.11(VDD) U4.33(VDD)
SRAM0_A0: U3.1(A0)
SRAM0_A1: U3.2(A1)
SRAM0_A2: U3.3(A2)
SRAM0_A3: U3.4(A3)
SRAM0_A4: U3.5(A4)
SRAM0_A5: U3.18(A5)
SRAM0_A6: U3.19(A6)
SRAM0_A7: U3.20(A7)
SRAM0_A8: U3.21(A8)
SRAM0_A9: U3.22(A9)
SRAM0_A10: U3.23(A10)
SRAM0_A11: U3.24(A11)
SRAM0_A12: U3.25(A12)
SRAM0_A13: U3.26(A13)
SRAM0_A14: U3.27(A14)
SRAM0_A15: U3.42(A15)
SRAM0_A16: U3.43(A16)
SRAM0_A17: U3.44(A17)
SRAM0_A18: U3.28(NC)
SRAM0_D0: U3.7(D0)
SRAM0_D1: U3.8(D1)
SRAM0_D2: U3.9(D2)
SRAM0_D3: U3.10(D3)
SRAM0_D4: U3.13(D4)
SRAM0_D5: U3.14(D5)
SRAM0_D6: U3.15(D6)
SRAM0_D7: U3.16(D7)
SRAM0_D8: U3.29(D8)
SRAM0_D9: U3.30(D9)
SRAM0_D10: U3.31(D10)
SRAM0_D11: U3.32(D11)
SRAM0_D12: U3.35(D12)
SRAM0_D13: U3.36(D13)
SRAM0_D14: U3.37(D14)
SRAM0_D15: U3.38(D15)
SRAM0_E: U3.6(~{CS}) ; port SRAM0_E
SRAM0_LB: U3.39(~{BLE}) ; port SRAM0_LB
SRAM0_OE: U3.41(~{OE}) ; port SRAM0_OE
SRAM0_UB: U3.40(~{BHE}) ; port SRAM0_UB
SRAM0_W: U3.17(~{WE}) ; port SRAM0_W
SRAM1_A0: U4.1(A0)
SRAM1_A1: U4.2(A1)
SRAM1_A2: U4.3(A2)
SRAM1_A3: U4.4(A3)
SRAM1_A4: U4.5(A4)
SRAM1_A5: U4.18(A5)
SRAM1_A6: U4.19(A6)
SRAM1_A7: U4.20(A7)
SRAM1_A8: U4.21(A8)
SRAM1_A9: U4.22(A9)
SRAM1_A10: U4.23(A10)
SRAM1_A11: U4.24(A11)
SRAM1_A12: U4.25(A12)
SRAM1_A13: U4.26(A13)
SRAM1_A14: U4.27(A14)
SRAM1_A15: U4.42(A15)
SRAM1_A16: U4.43(A16)
SRAM1_A17: U4.44(A17)
SRAM1_A18: U4.28(NC)
SRAM1_D0: U4.7(D0)
SRAM1_D1: U4.8(D1)
SRAM1_D2: U4.9(D2)
SRAM1_D3: U4.10(D3)
SRAM1_D4: U4.13(D4)
SRAM1_D5: U4.14(D5)
SRAM1_D6: U4.15(D6)
SRAM1_D7: U4.16(D7)
SRAM1_D8: U4.29(D8)
SRAM1_D9: U4.30(D9)
SRAM1_D10: U4.31(D10)
SRAM1_D11: U4.32(D11)
SRAM1_D12: U4.35(D12)
SRAM1_D13: U4.36(D13)
SRAM1_D14: U4.37(D14)
SRAM1_D15: U4.38(D15)
SRAM1_E: U4.6(~{CS}) ; port SRAM1_E
SRAM1_LB: U4.39(~{BLE}) ; port SRAM1_LB
SRAM1_OE: U4.41(~{OE}) ; port SRAM1_OE
SRAM1_UB: U4.40(~{BHE}) ; port SRAM1_UB
SRAM1_W: U4.17(~{WE}) ; port SRAM1_W

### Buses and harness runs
bus SRAM0_A[18..0] = port SRAM0_A[18..0]
bus SRAM0_D[15..0] = port SRAM0_D[15..0]
bus SRAM1_A[18..0] = port SRAM1_A[18..0]
bus SRAM1_D[15..0] = port SRAM1_D[15..0]

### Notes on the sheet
- 80 PINS
- A18 is connected so that 512KBx16 device can be fitted
- INDEPENDENT SRAM

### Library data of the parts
C49 C50 = CAP-P: Polar Capacitor
C51-C58 = CAP-NP: Capacitor
U3 U4 = K6R4016V1D-T: 256Kx16Bit SRAM TSOP44

## Sheet Multi-channel_diff-pairs.SchDoc: Pin Swapping
size 431 x 279 mm
Used 4 times, as channels ch1, ch2, ch3, ch4. Parts and nets are listed once, with the designators drawn on the sheet.
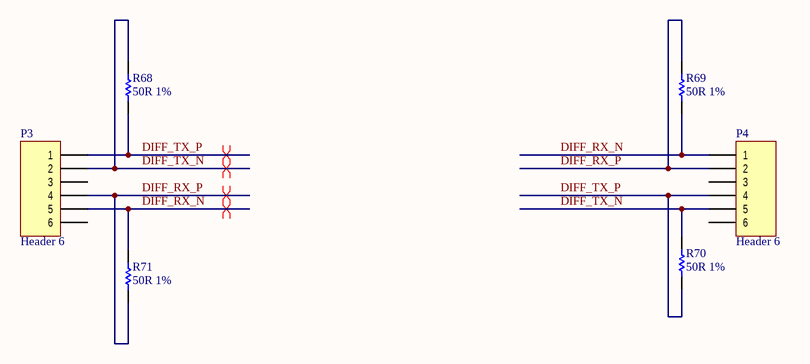
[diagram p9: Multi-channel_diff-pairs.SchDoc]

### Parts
P3  Header 6  [HDR1X6]
P4  Header 6  [HDR1X6]
R68  50R 1%  [RESC2012]
R69  50R 1%  [RESC2012]
R70  50R 1%  [RESC2012]
R71  50R 1%  [RESC2012]

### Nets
DIFF_RX_N: P3.5 P4.1 R69.2 R71.1
DIFF_RX_P: P3.4 P4.2 R69.1 R71.2
DIFF_TX_N: P3.2 P4.5 R68.1 R70.1
DIFF_TX_P: P3.1 P4.4 R68.2 R70.2

Not connected (* = marked no-connect by the designer): P3 3 6; P4 3 6

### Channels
ch1: designators end in _ch1
ch2: designators end in _ch2
ch3: designators end in _ch3
ch4: designators end in _ch4

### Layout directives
differential pair: DIFF_RX_N_ch1, DIFF_RX_P_ch1, DIFF_TX_N_ch1, DIFF_TX_P_ch1

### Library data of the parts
P3 P4 = Header 6: Header, 6-Pin
R68-R71 = RES: Resistor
